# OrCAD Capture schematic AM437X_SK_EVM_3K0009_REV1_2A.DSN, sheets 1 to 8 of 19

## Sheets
1 Pg09: Ethernet #2: size C; title: AM437x Starter Kit EVM; rev: 1.2A; company: Texas Instruments; note: am437x_starterkit_evm_3k0009.dsn; note: Catalog Processors BU; note: Final
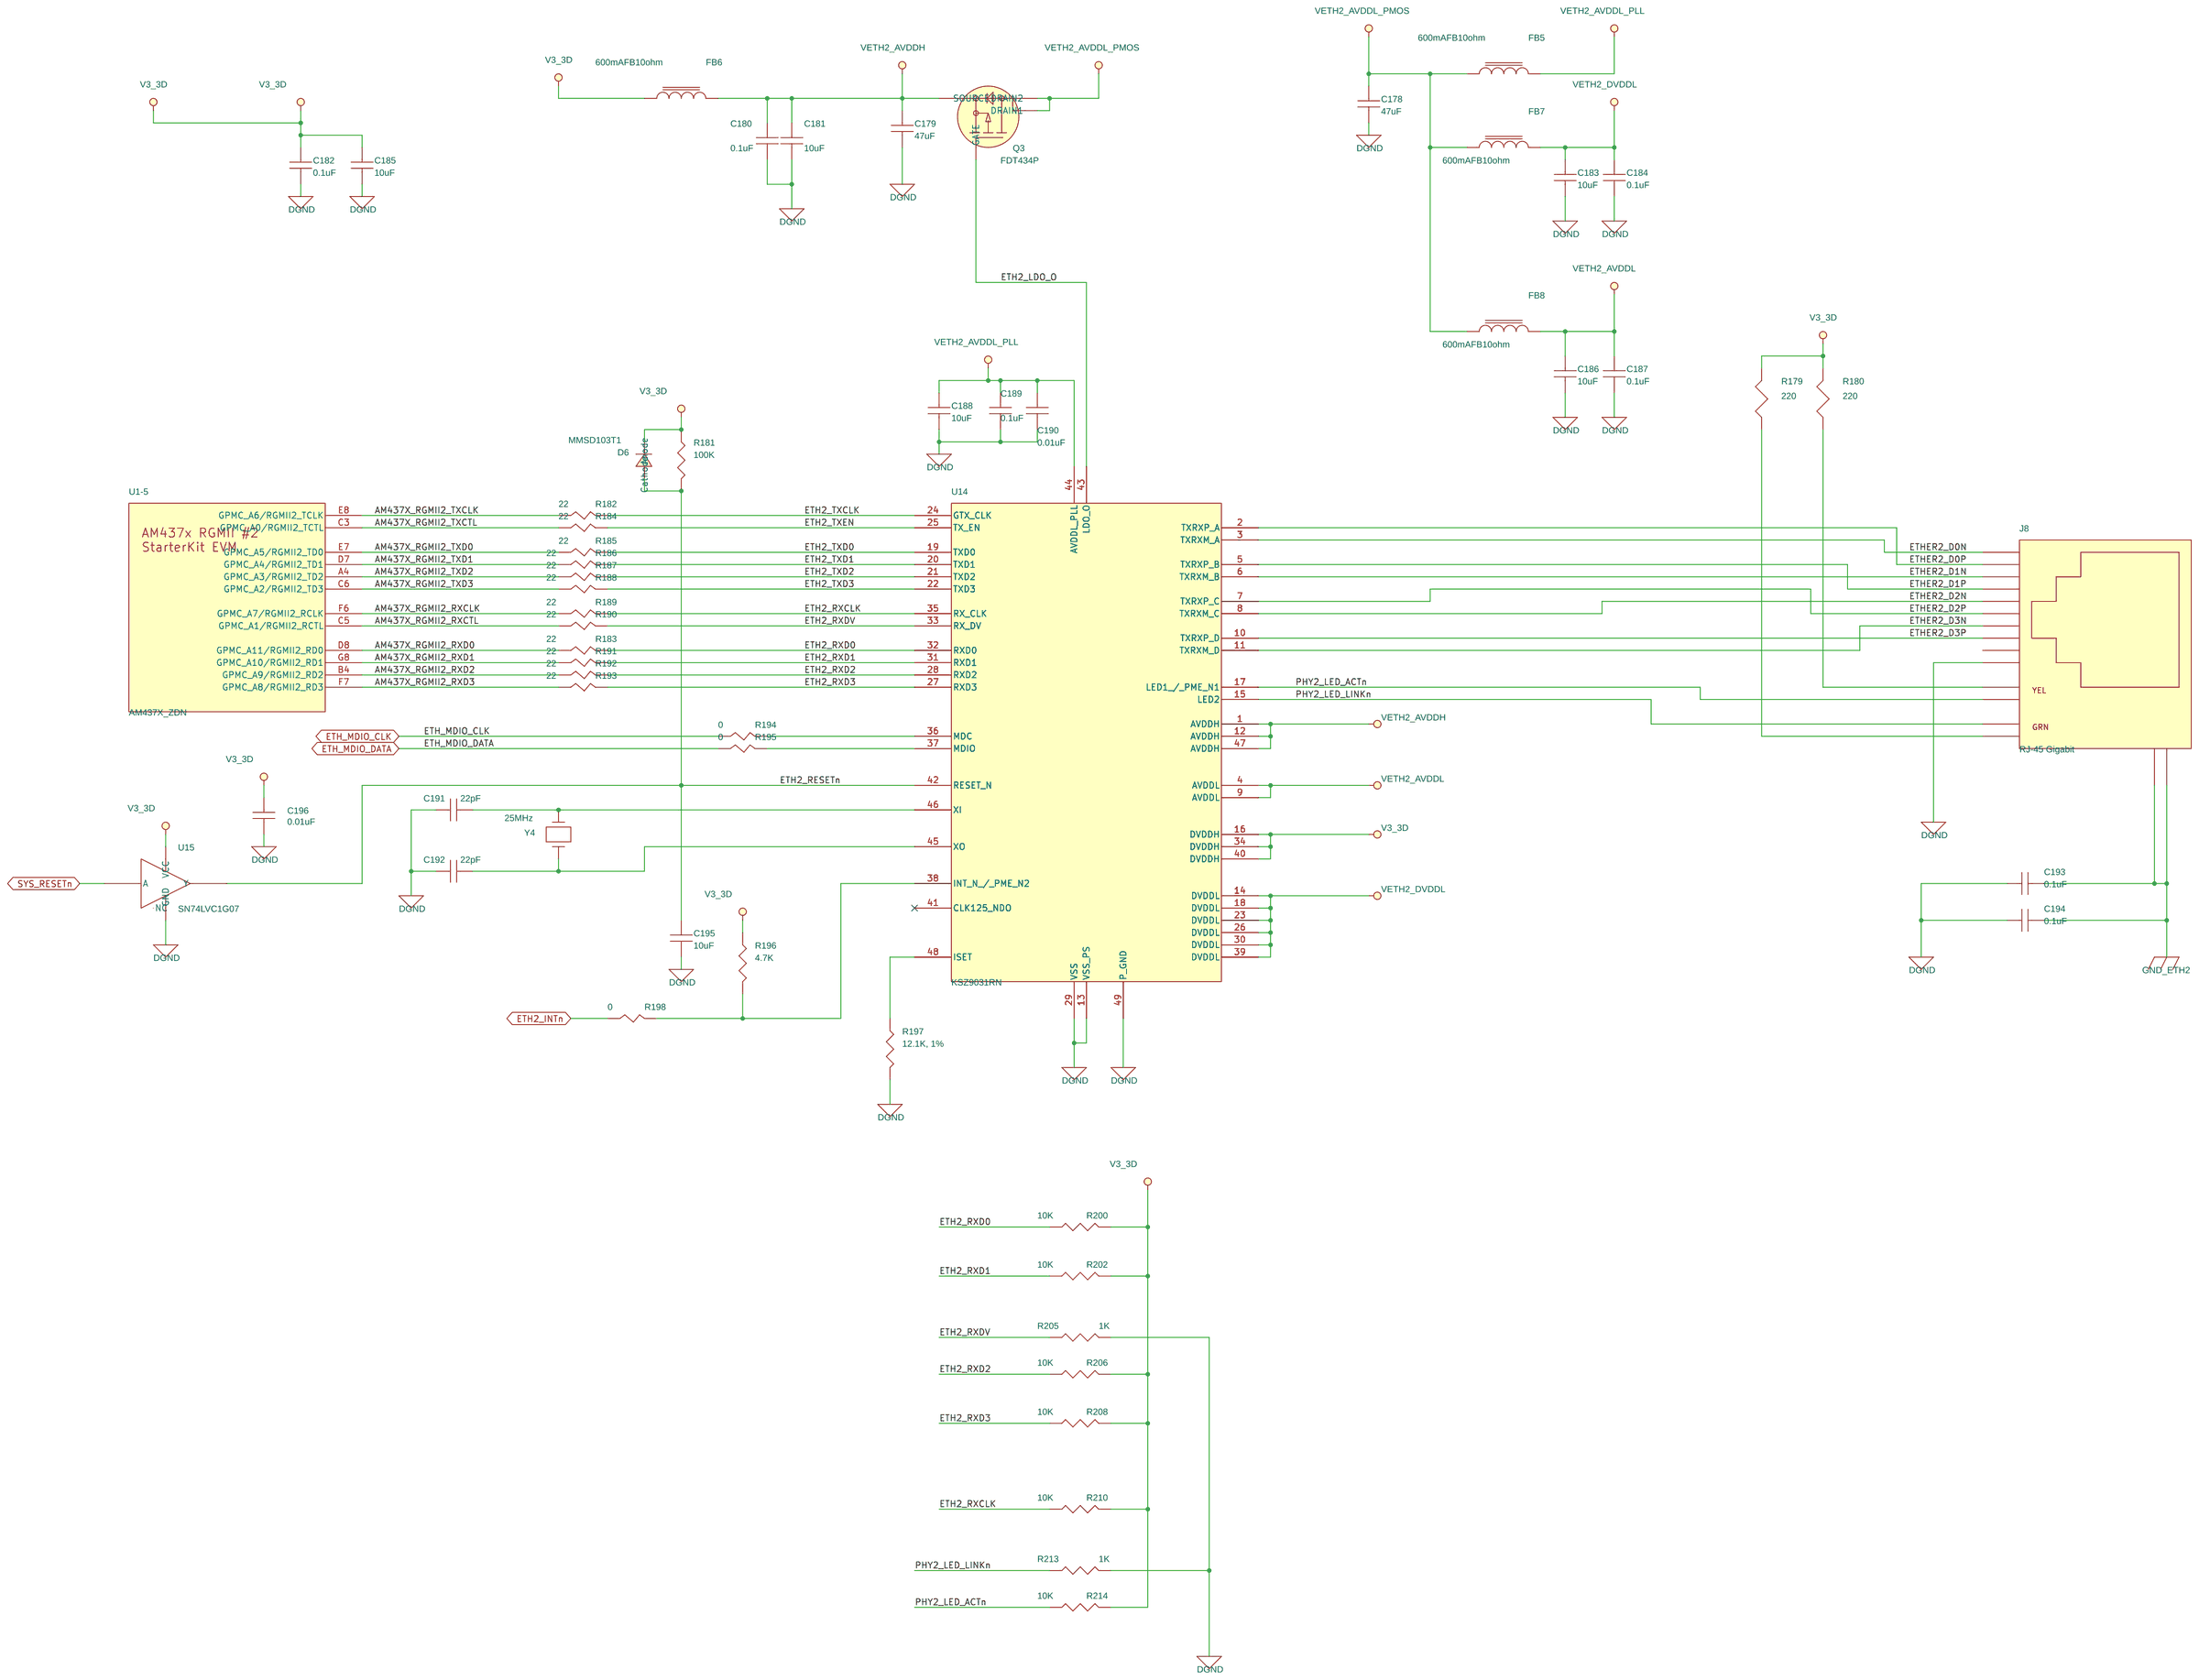
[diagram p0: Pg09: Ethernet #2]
2 Pg01: Title Page
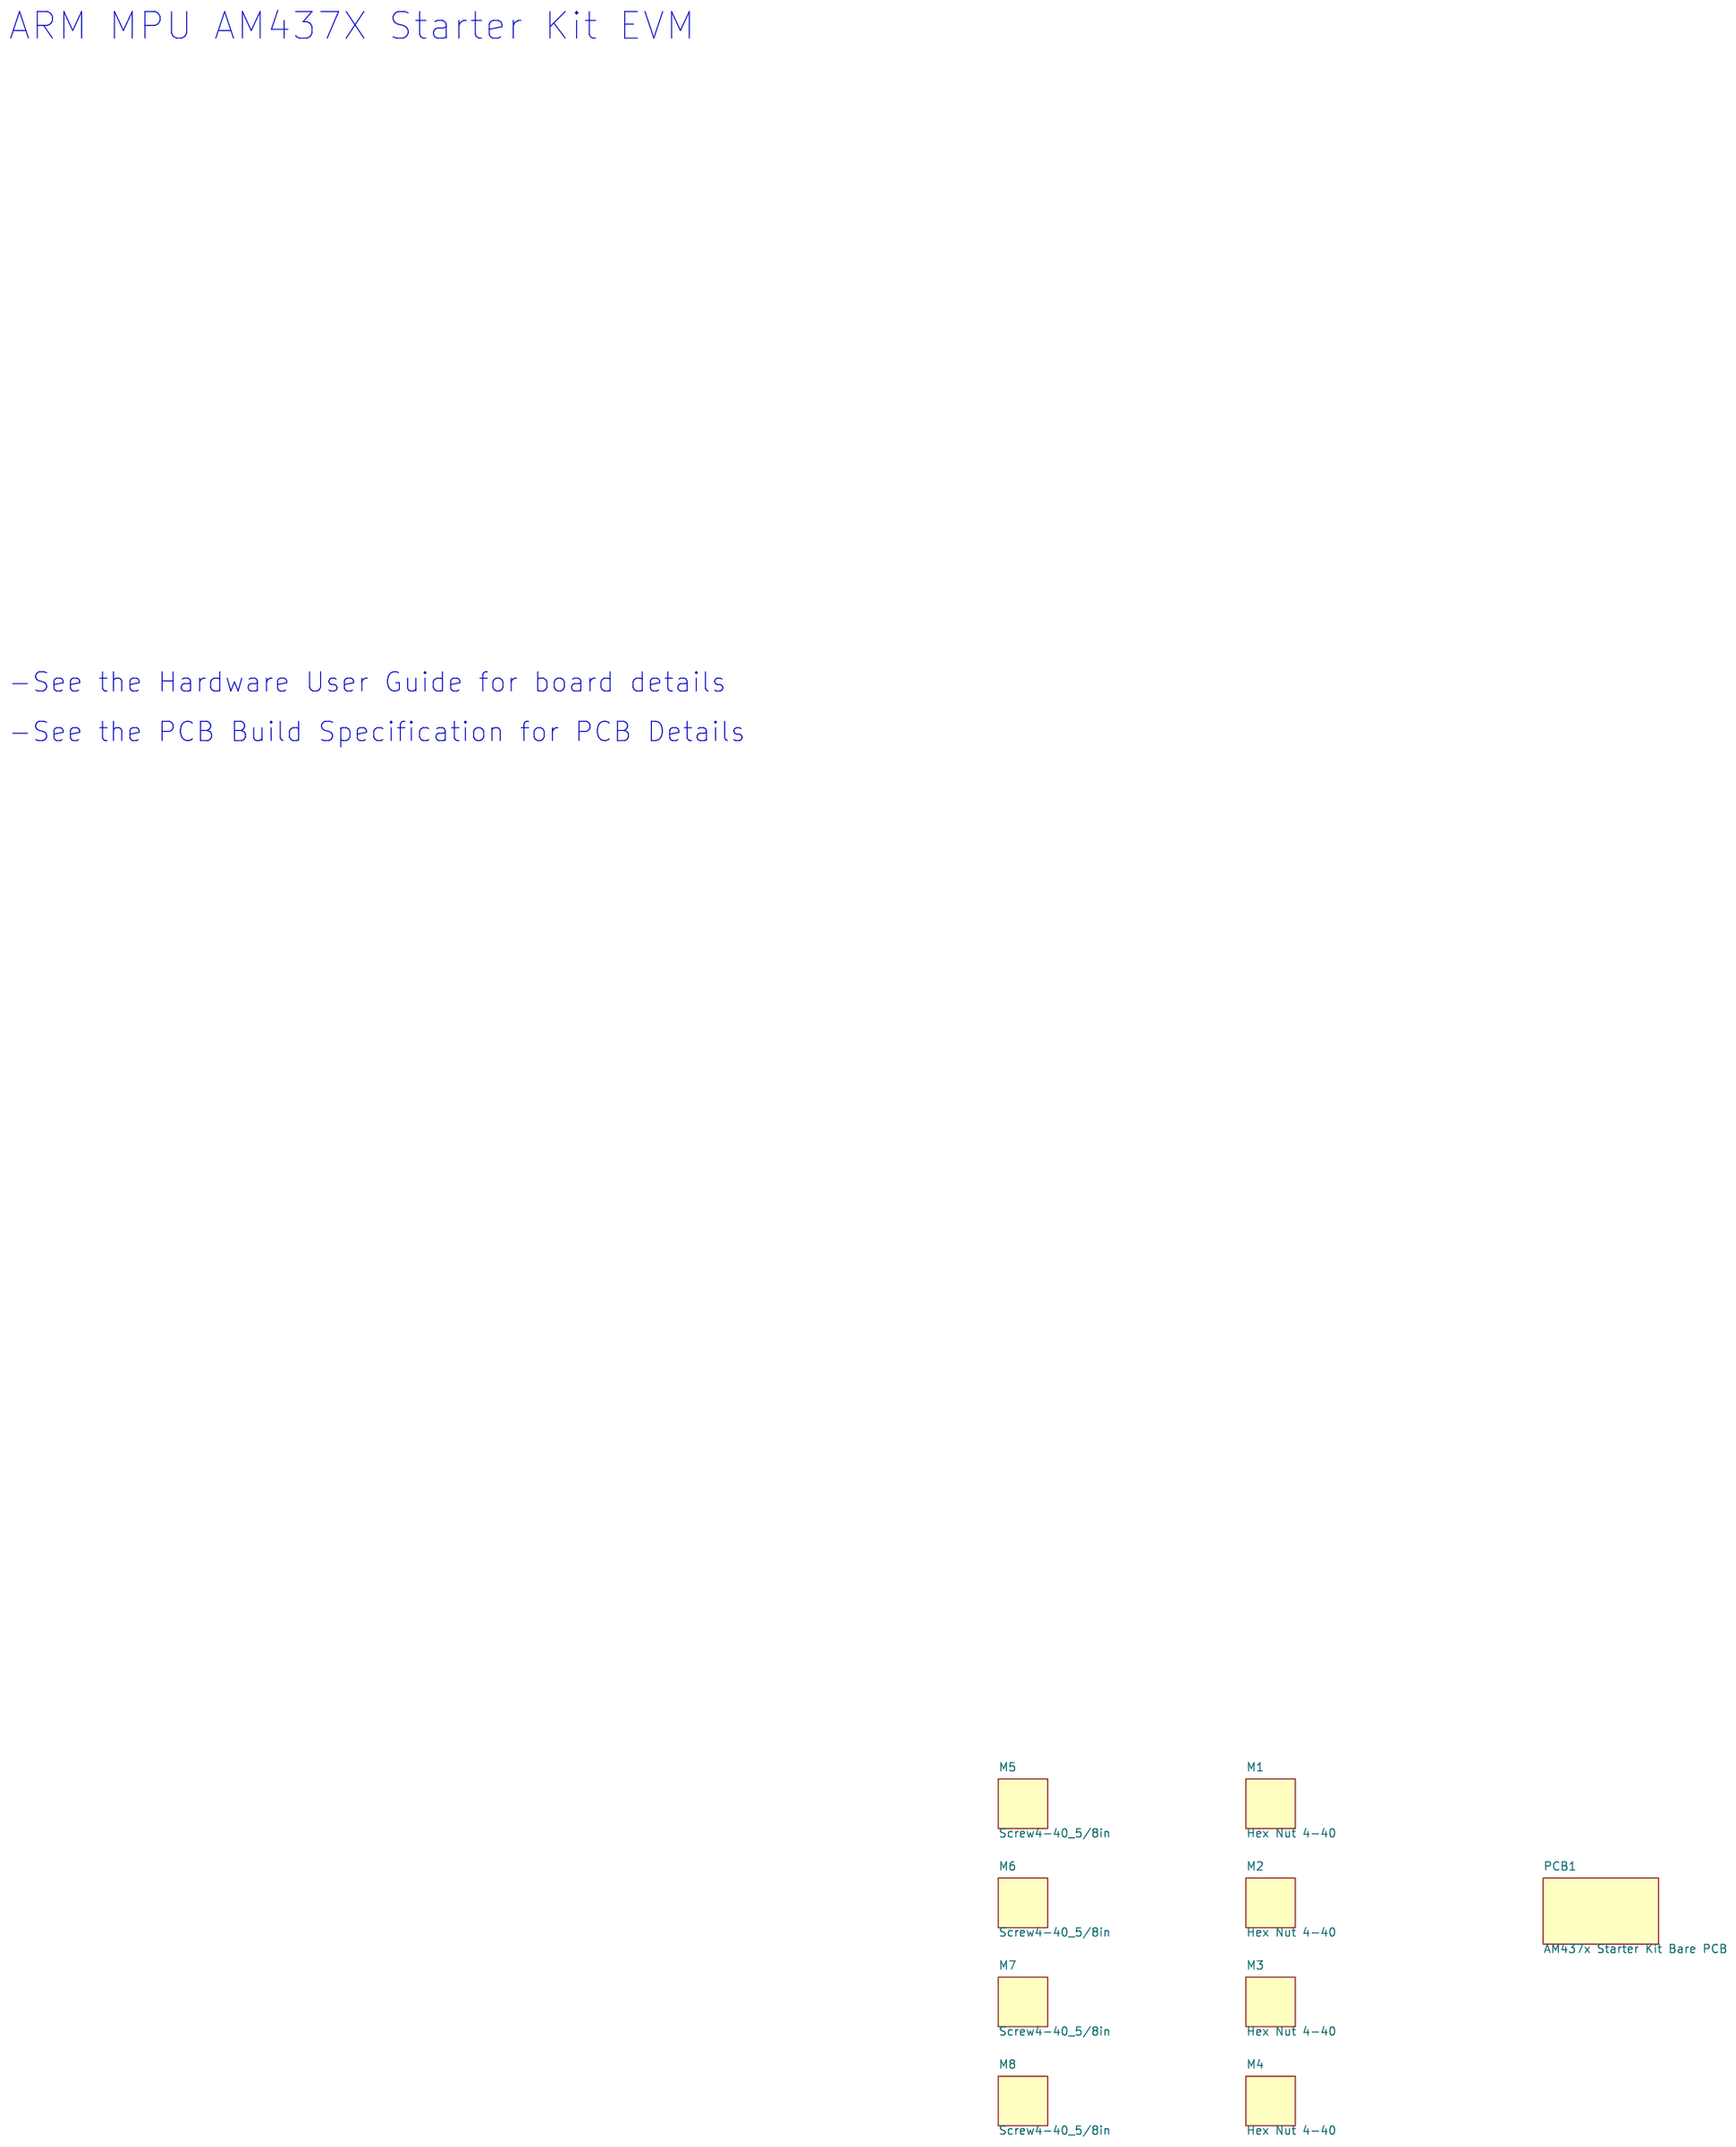
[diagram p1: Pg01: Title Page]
3 Pg12: Camera: size C
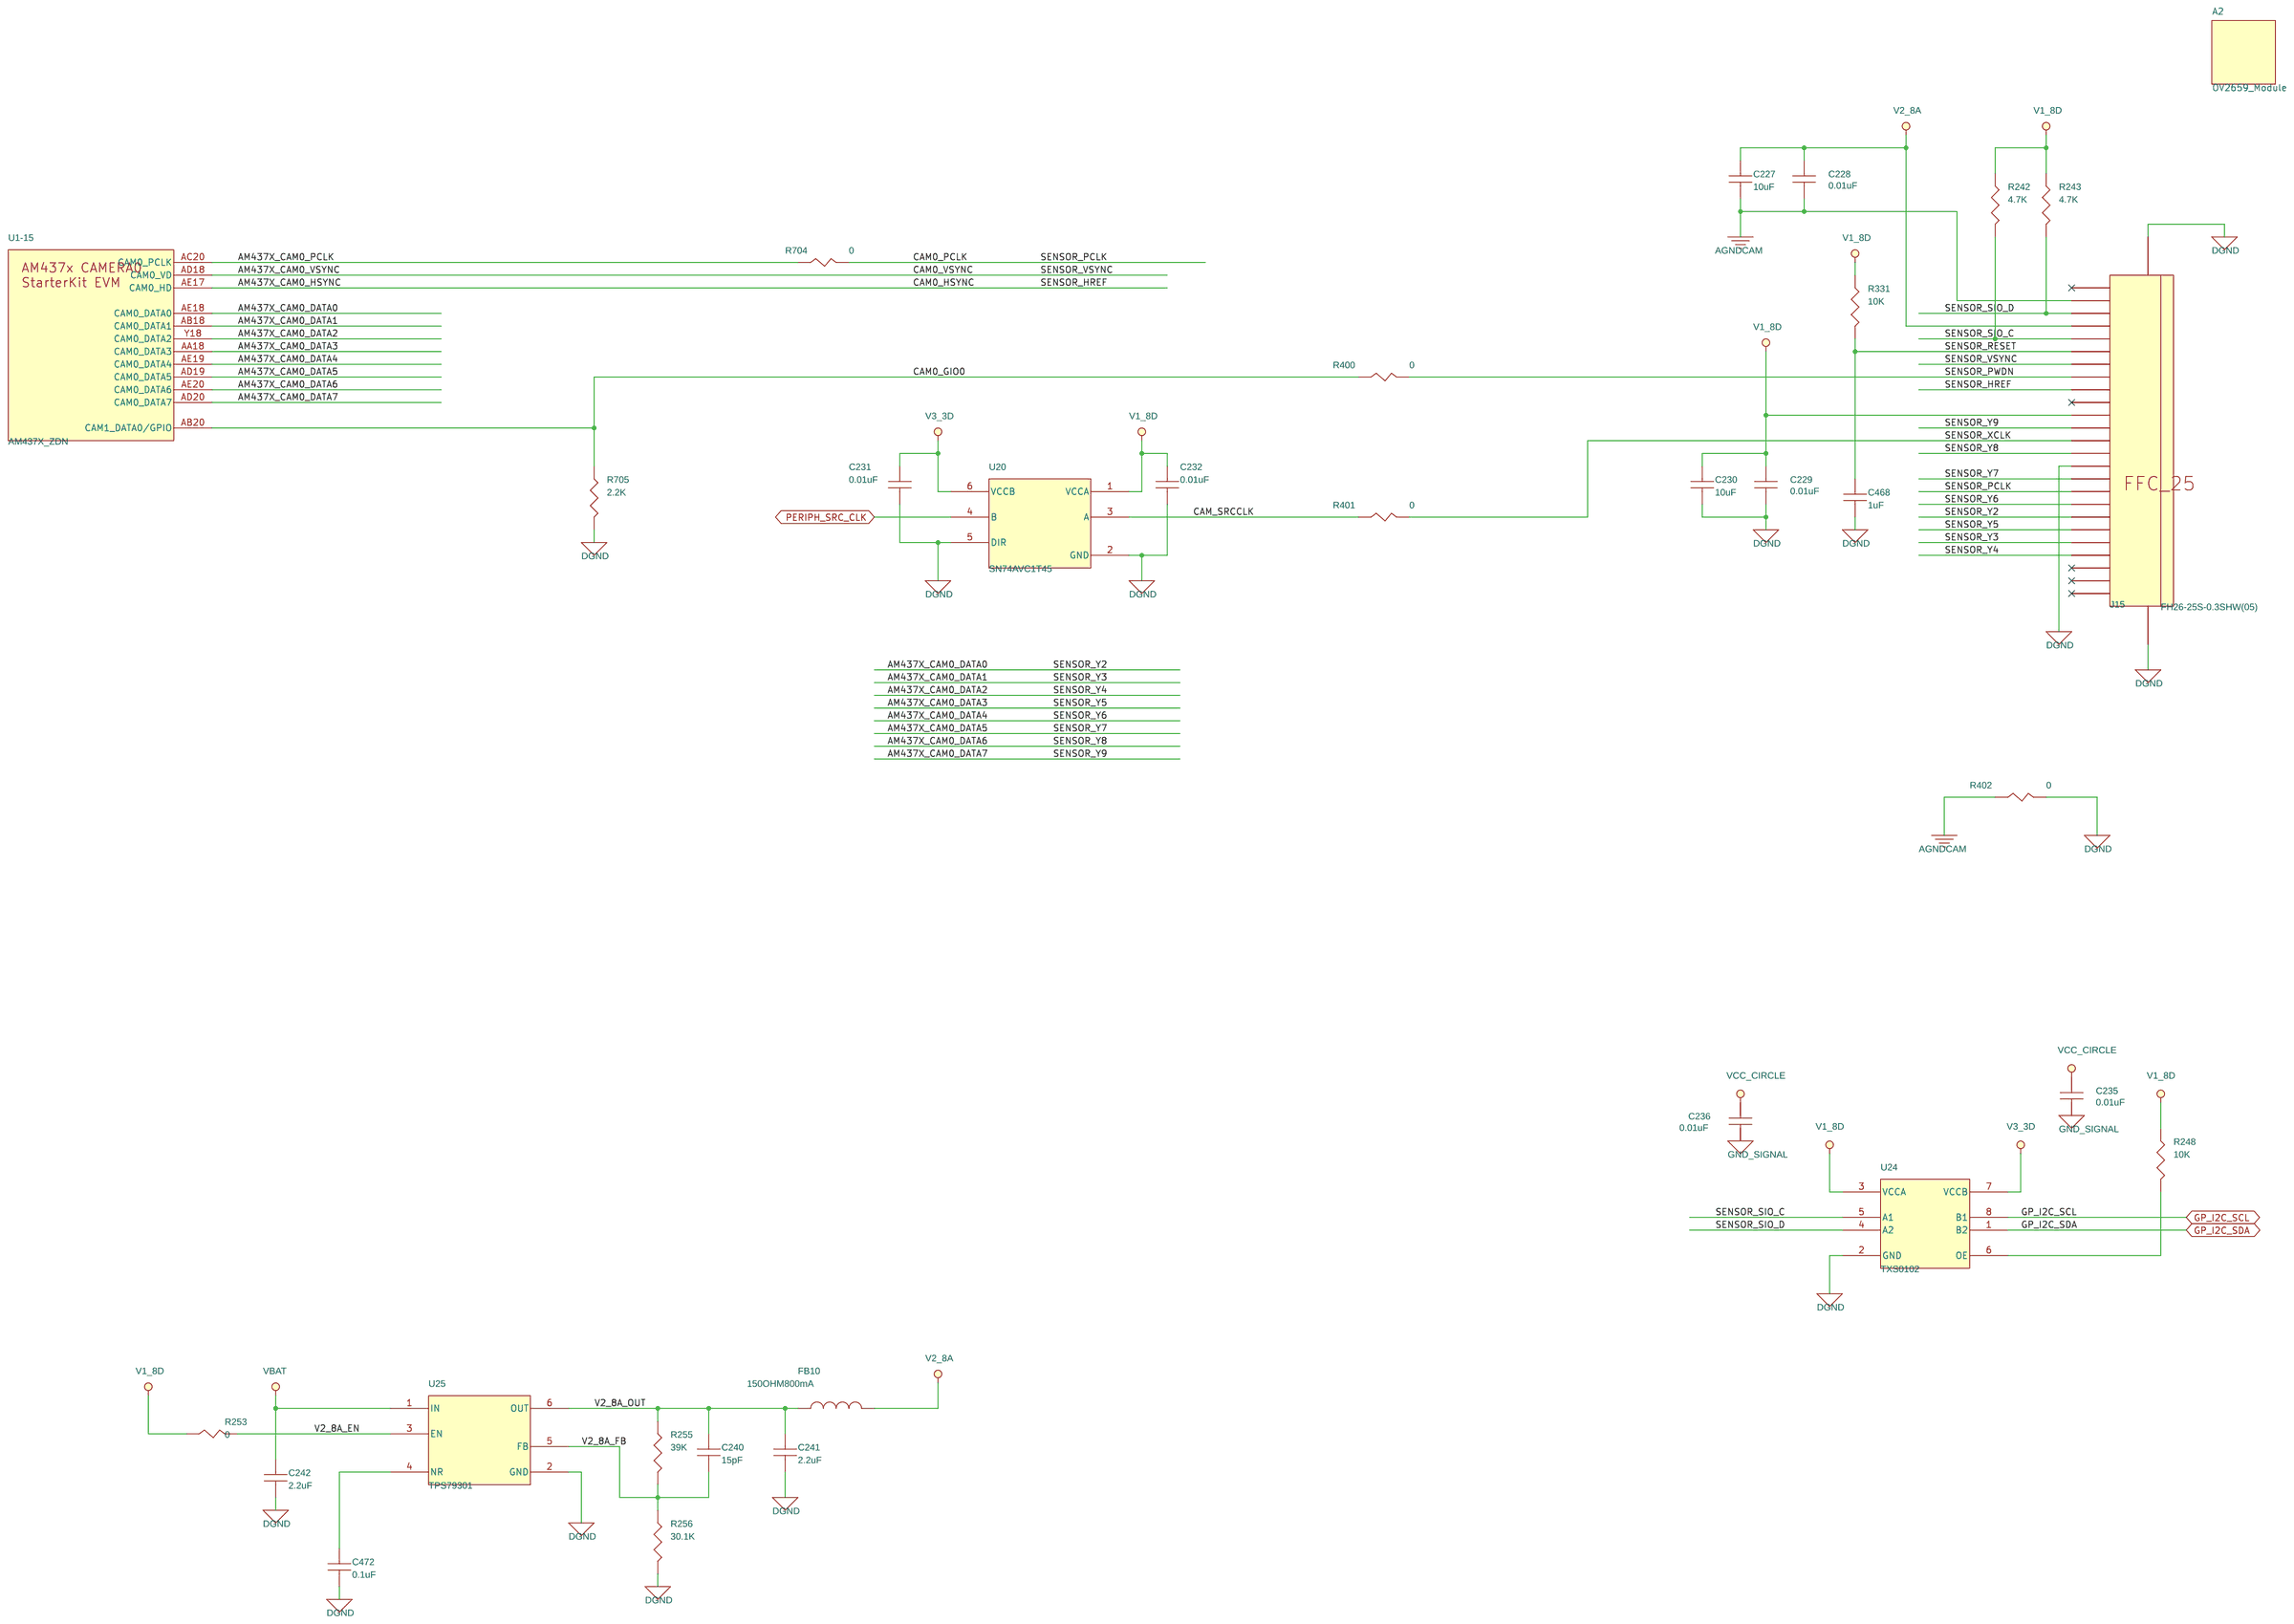
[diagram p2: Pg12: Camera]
4 Pg10: Audio: size C
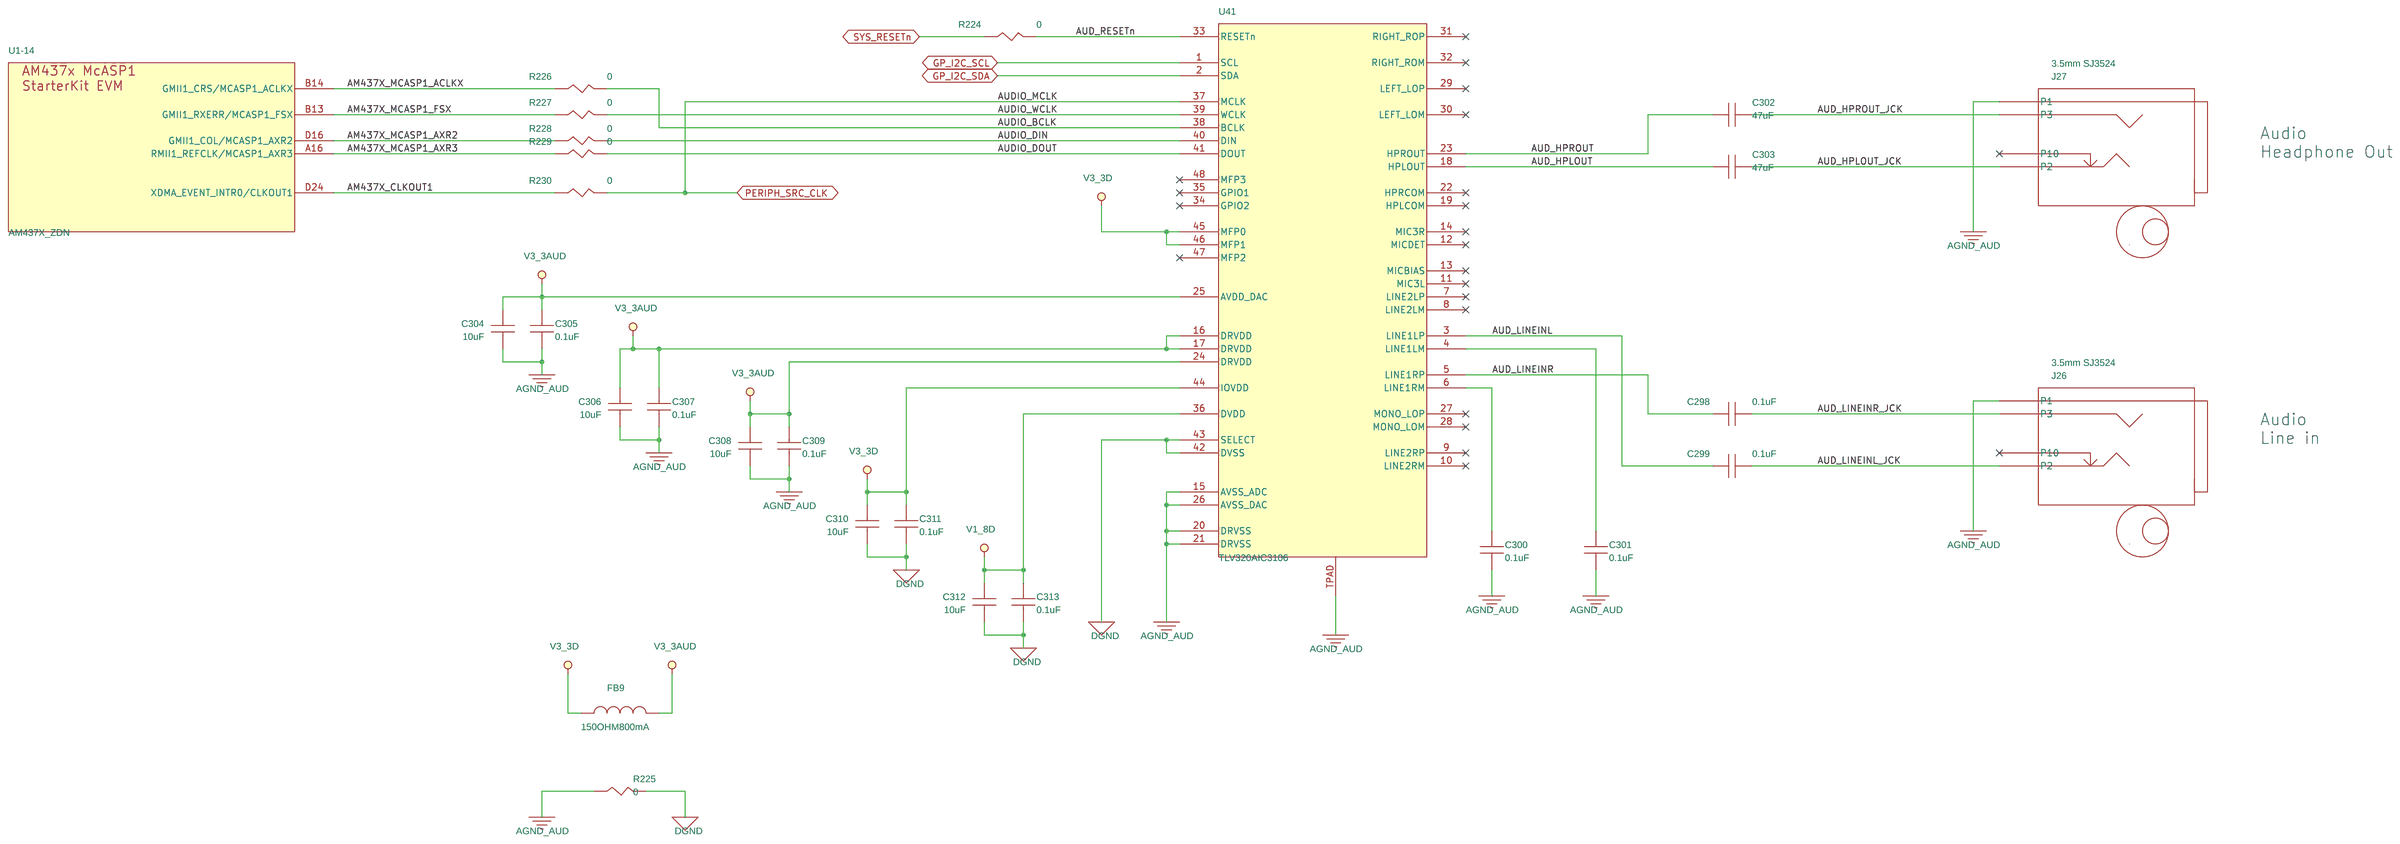
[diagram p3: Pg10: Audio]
5 Pg19: USB JTAG: size C
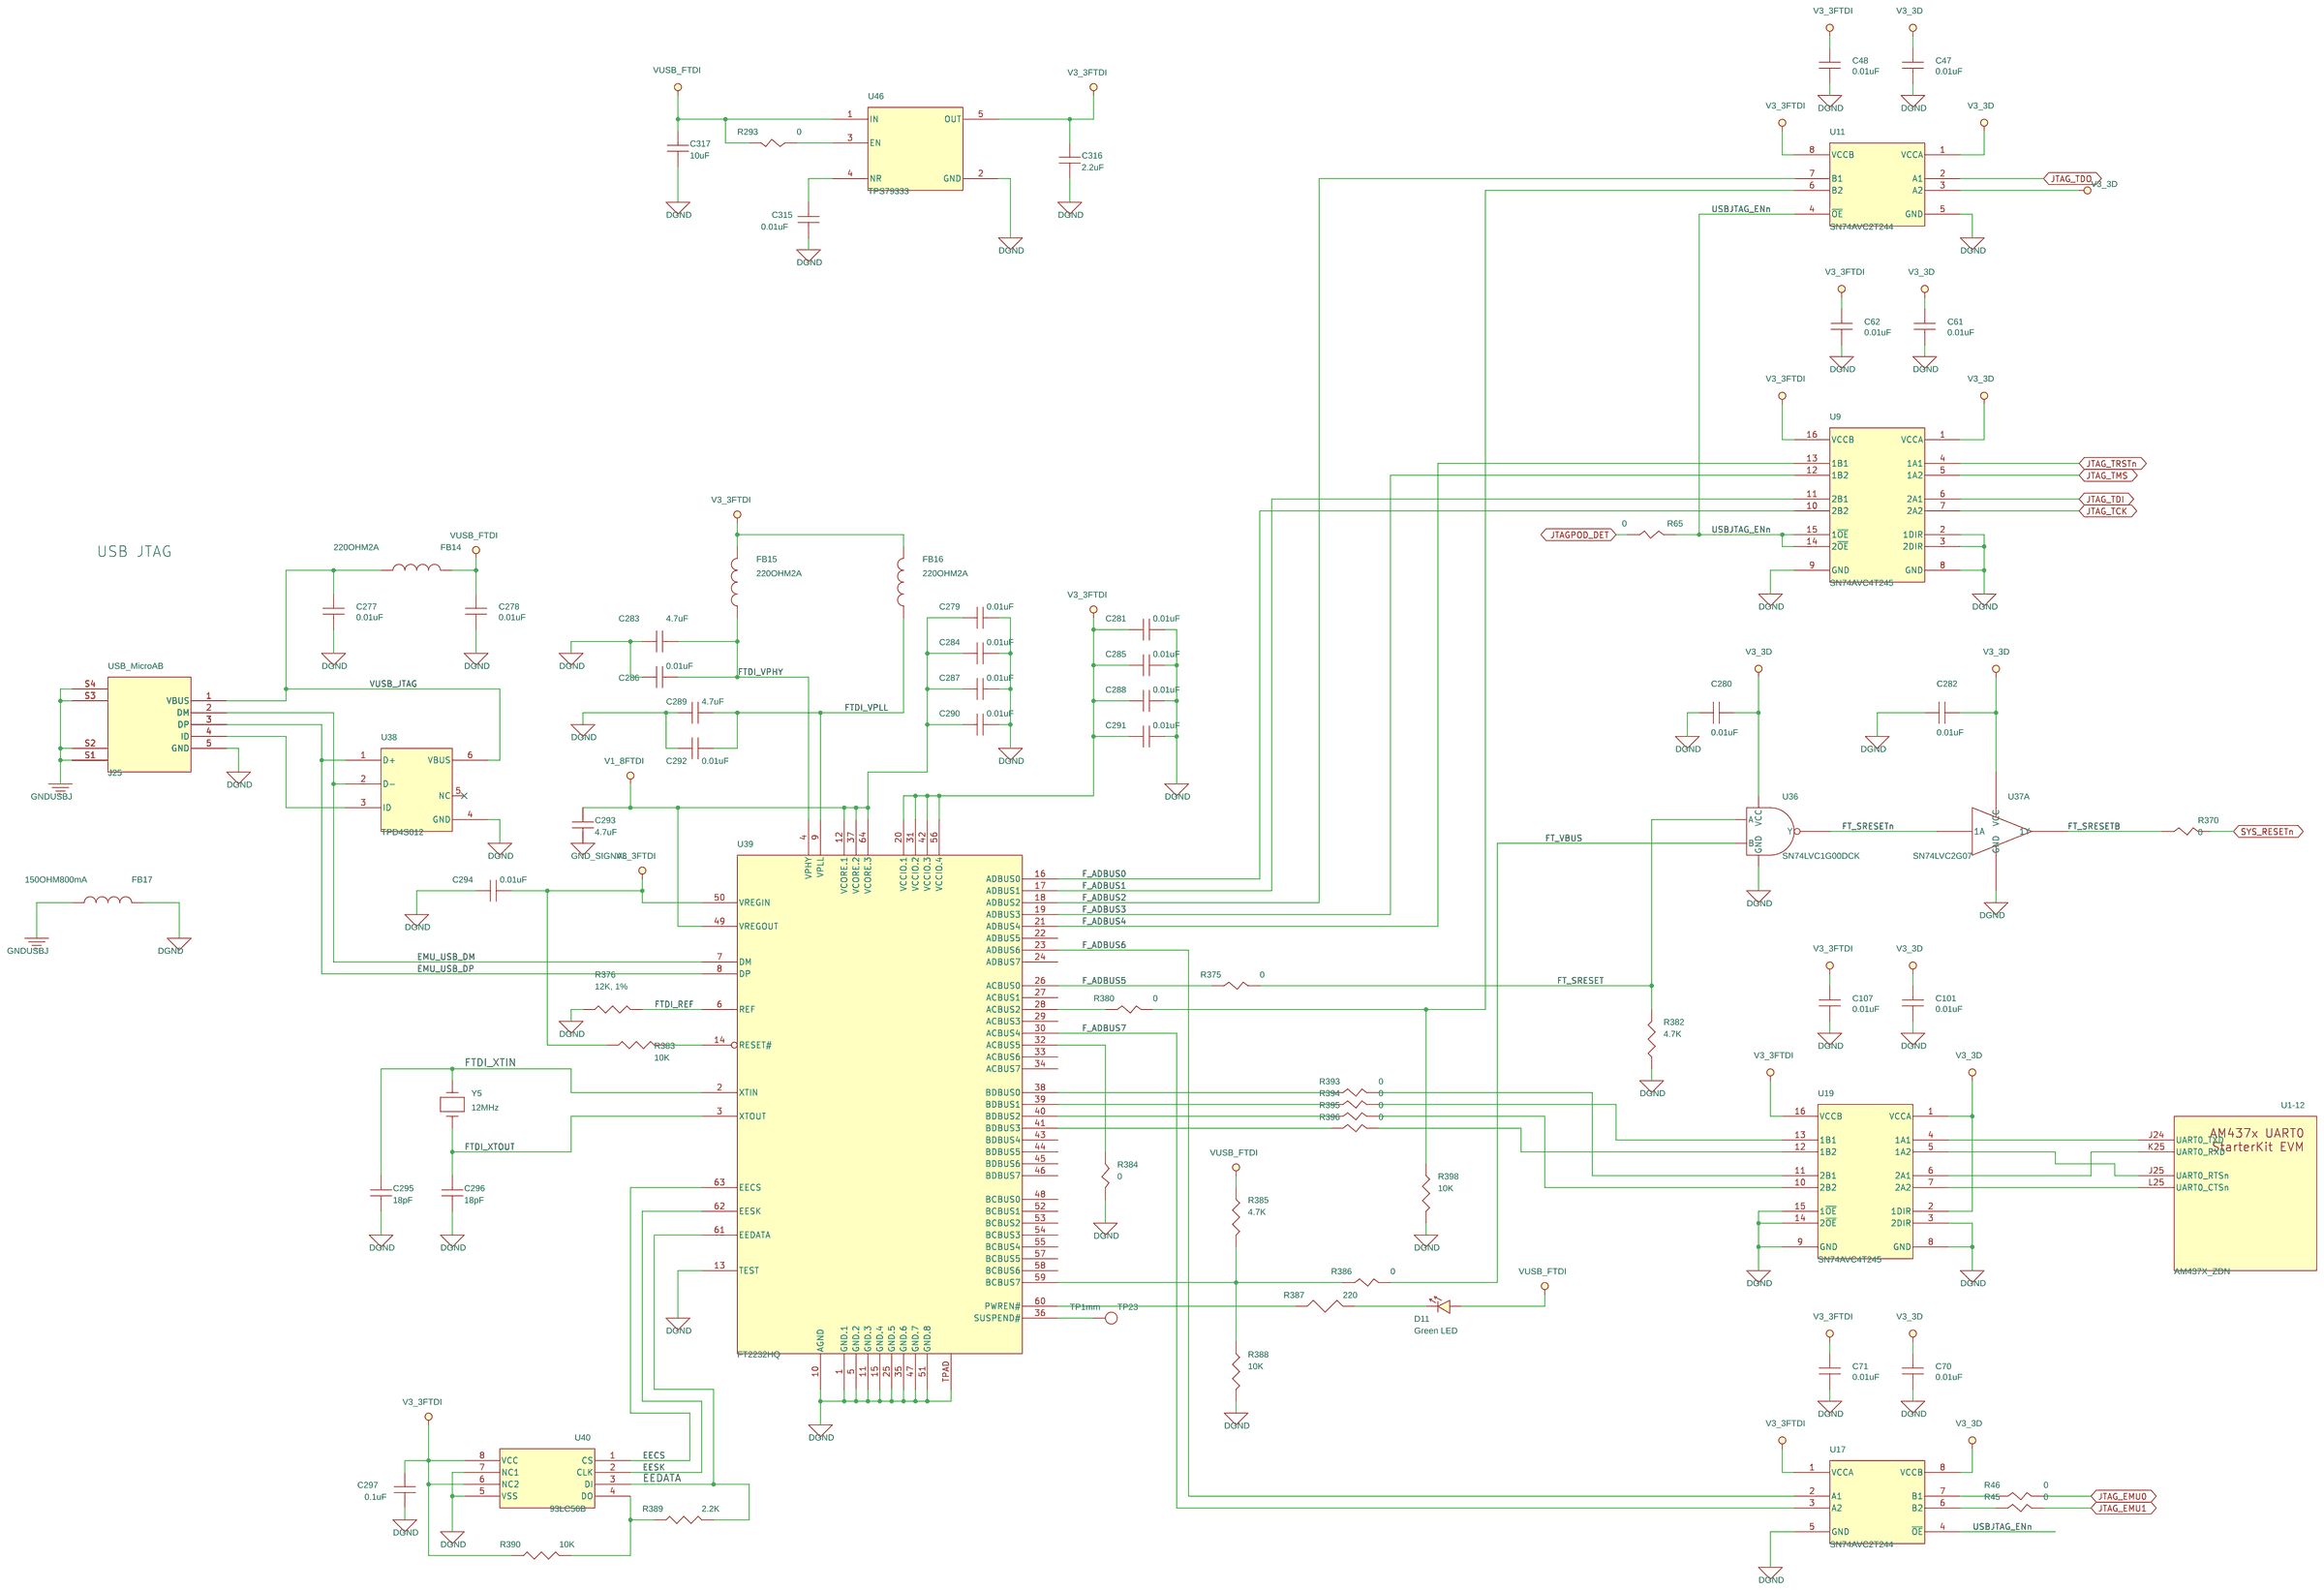
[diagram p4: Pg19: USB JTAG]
6 Pg06: DDR3 Memory: size C
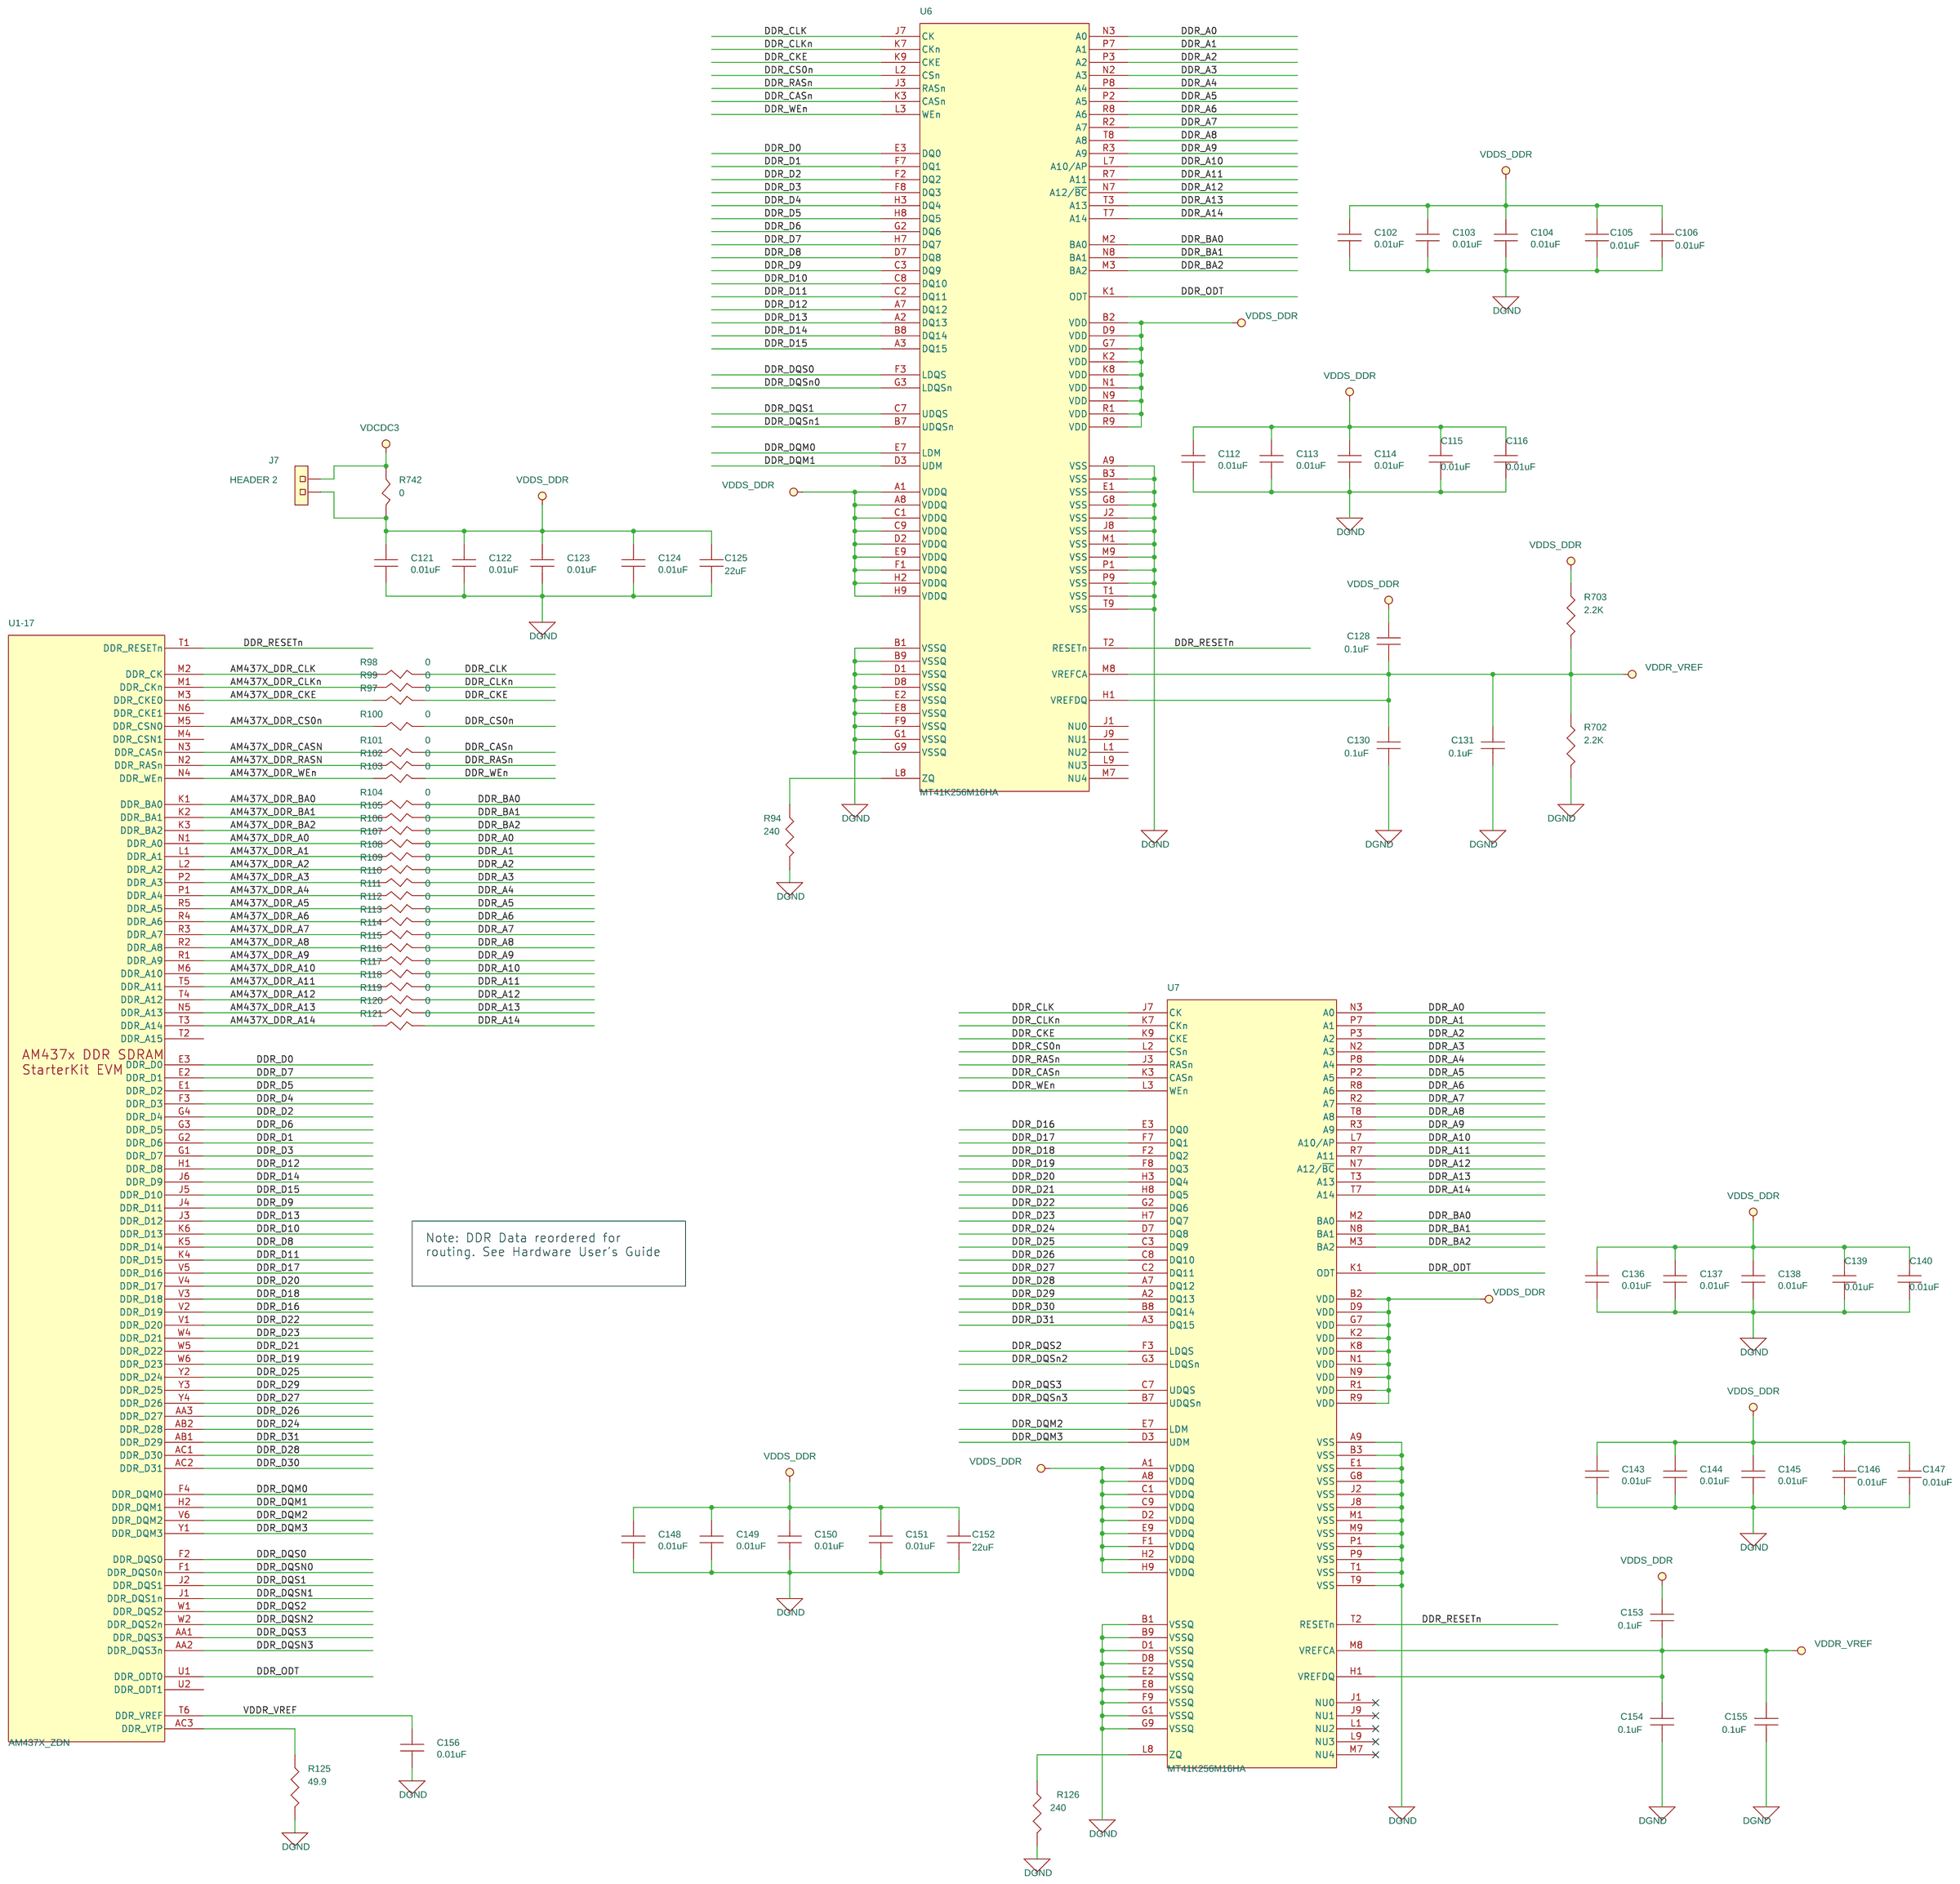
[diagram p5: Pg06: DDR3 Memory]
7 Pg18: JTAG Debug: size C
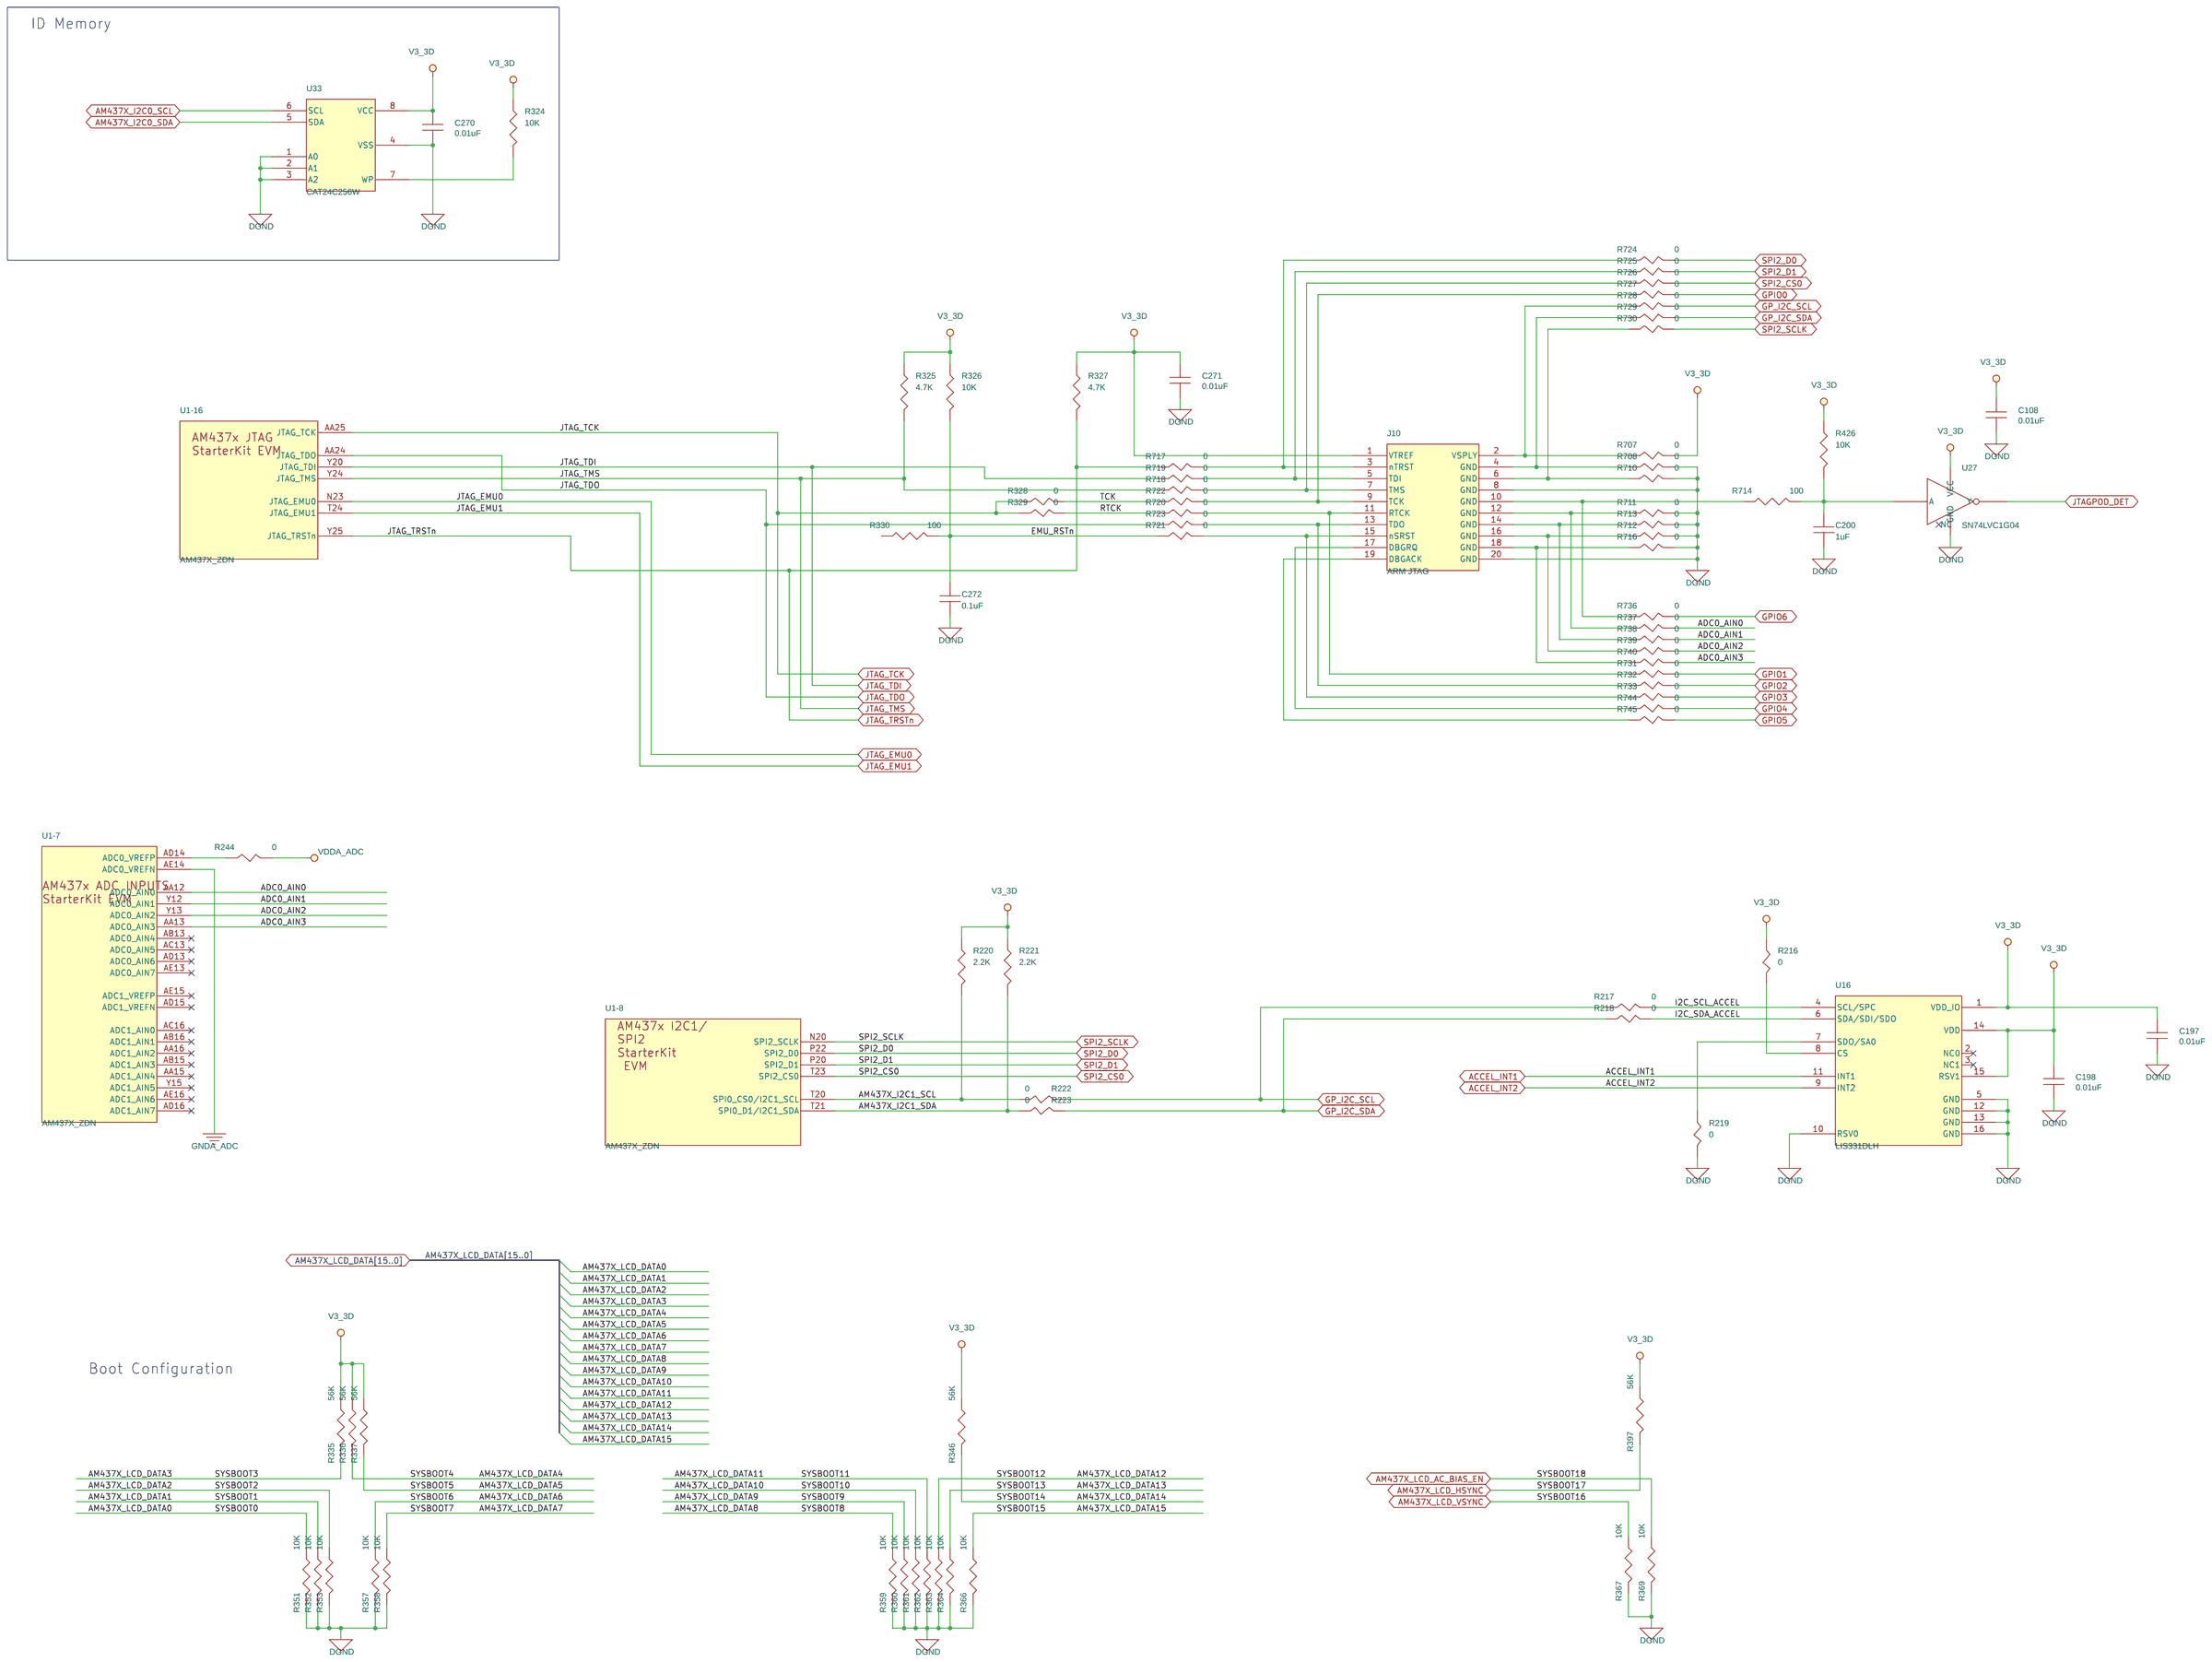
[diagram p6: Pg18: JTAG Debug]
8 Pg08: Ethernet #1: size C
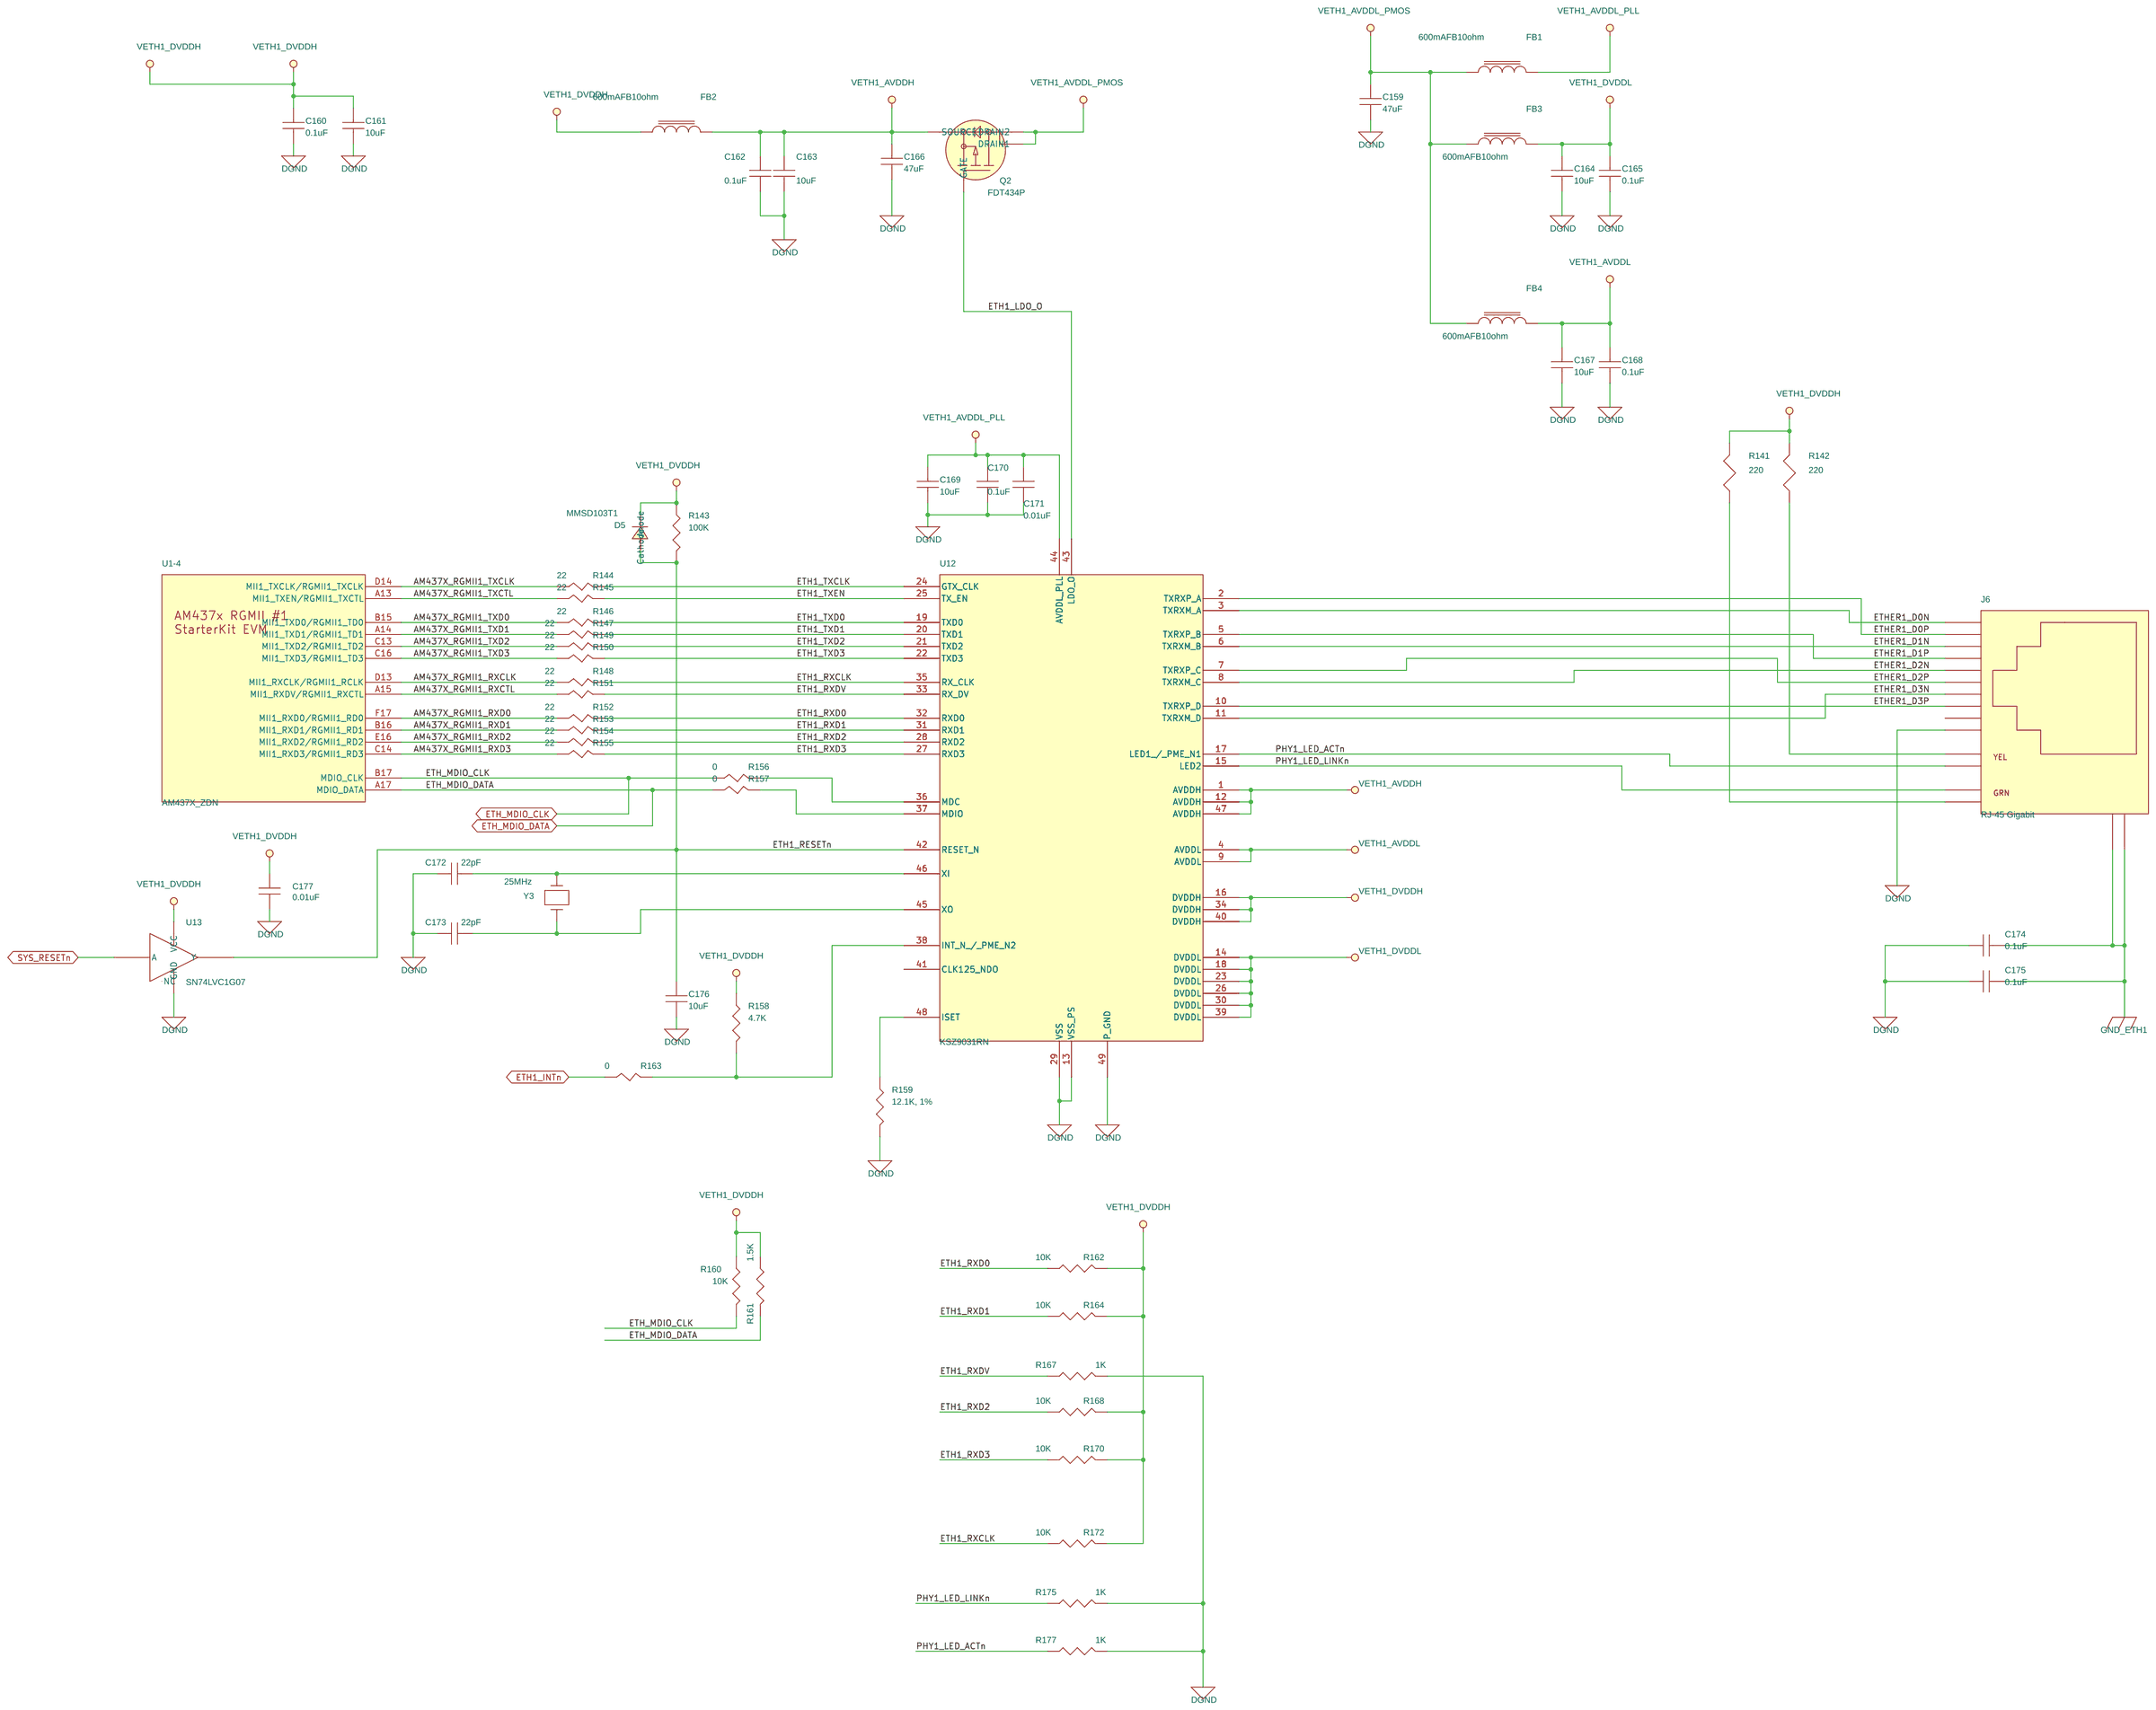
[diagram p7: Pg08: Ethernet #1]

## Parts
sheet Pg01: Title Page
M1  Hex Nut 4-40  [DNP]
M2  Hex Nut 4-40  [DNP]
M3  Hex Nut 4-40  [DNP]
M4  Hex Nut 4-40  [DNP]
M5  Screw4-40_5/8in  [DNP]
M6  Screw4-40_5/8in  [DNP]
M7  Screw4-40_5/8in  [DNP]
M8  Screw4-40_5/8in  [DNP]
PCB1  AM437x Starter Kit Bare PCB  [DNP]
sheet Pg04: Power Supply - PMIC
U1  AM437X_ZDN  [AM437X_ZDN]  (sections -1,-10,-11,-12,-13,-14,-15,-16,-17,-18,-19,-2,-20,-21,-3,-4,-5,-6,-7,-8,-9)
sheet Pg06: DDR3 Memory
C102  0.01uF  [SM-7351-CAP-0402]
C103  0.01uF  [SM-7351-CAP-0402]
C104  0.01uF  [SM-7351-CAP-0402]
C105  0.01uF  [SM-7351-CAP-0402]
C106  0.01uF  [SM-7351-CAP-0402]
C112  0.01uF  [SM-7351-CAP-0402]
C113  0.01uF  [SM-7351-CAP-0402]
C114  0.01uF  [SM-7351-CAP-0402]
C115  0.01uF  [SM-7351-CAP-0402]
C116  0.01uF  [SM-7351-CAP-0402]
C121  0.01uF  [SM-7351-CAP-0402]
C122  0.01uF  [SM-7351-CAP-0402]
C123  0.01uF  [SM-7351-CAP-0402]
C124  0.01uF  [SM-7351-CAP-0402]
C125  22uF  [SM-7351-CAP-0805]
C128  0.1uF  [SM-7351-CAP-0402]
C130  0.1uF  [SM-7351-CAP-0402]
C131  0.1uF  [SM-7351-CAP-0402]
C136  0.01uF  [SM-7351-CAP-0402]
C137  0.01uF  [SM-7351-CAP-0402]
C138  0.01uF  [SM-7351-CAP-0402]
C139  0.01uF  [SM-7351-CAP-0402]
C140  0.01uF  [SM-7351-CAP-0402]
C143  0.01uF  [SM-7351-CAP-0402]
C144  0.01uF  [SM-7351-CAP-0402]
C145  0.01uF  [SM-7351-CAP-0402]
C146  0.01uF  [SM-7351-CAP-0402]
C147  0.01uF  [SM-7351-CAP-0402]
C148  0.01uF  [SM-7351-CAP-0402]
C149  0.01uF  [SM-7351-CAP-0402]
C150  0.01uF  [SM-7351-CAP-0402]
C151  0.01uF  [SM-7351-CAP-0402]
C152  22uF  [SM-7351-CAP-0805]
C153  0.1uF  [SM-7351-CAP-0402]
C154  0.1uF  [SM-7351-CAP-0402]
C155  0.1uF  [SM-7351-CAP-0402]
C156  0.01uF  [SM-7351-CAP-0402]
J7  HEADER 2  [header_2x1]
R94  240  [sm-7351-res-0402]
R97  0  [SM-7351-RES-0402]
R98  0  [SM-7351-RES-0402]
R99  0  [SM-7351-RES-0402]
R100  0  [SM-7351-RES-0402]
R101  0  [SM-7351-RES-0402]
R102  0  [SM-7351-RES-0402]
R103  0  [SM-7351-RES-0402]
R104  0  [SM-7351-RES-0402]
R105  0  [SM-7351-RES-0402]
R106  0  [SM-7351-RES-0402]
R107  0  [SM-7351-RES-0402]
R108  0  [SM-7351-RES-0402]
R109  0  [SM-7351-RES-0402]
R110  0  [SM-7351-RES-0402]
R111  0  [SM-7351-RES-0402]
R112  0  [SM-7351-RES-0402]
R113  0  [SM-7351-RES-0402]
R114  0  [SM-7351-RES-0402]
R115  0  [SM-7351-RES-0402]
R116  0  [SM-7351-RES-0402]
R117  0  [SM-7351-RES-0402]
R118  0  [SM-7351-RES-0402]
R119  0  [SM-7351-RES-0402]
R120  0  [SM-7351-RES-0402]
R121  0  [SM-7351-RES-0402]
R125  49.9  [SM-7351-RES-0402]
R126  240  [sm-7351-res-0402]
R702  2.2K  [sm-7351-res-0402]
R703  2.2K  [sm-7351-res-0402]
R742  0  [SM-7351-RES-0402]
U6  MT41K256M16HA  [bga9x14-96]
U7  MT41K256M16HA  [bga9x14-96]
sheet Pg08: Ethernet #1
C159  47uF  [SM-7351-CAP-1206]
C160  0.1uF  [SM-7351-CAP-0402]
C161  10uF  [SM-7351-CAP-0805]
C162  0.1uF  [SM-7351-CAP-0402]
C163  10uF  [SM-7351-CAP-0805]
C164  10uF  [SM-7351-CAP-0805]
C165  0.1uF  [SM-7351-CAP-0402]
C166  47uF  [SM-7351-CAP-1206]
C167  10uF  [SM-7351-CAP-0805]
C168  0.1uF  [SM-7351-CAP-0402]
C169  10uF  [SM-7351-CAP-0805]
C170  0.1uF  [SM-7351-CAP-0402]
C171  0.01uF  [SM-7351-CAP-0402]
C172  22pF  [SM-7351-CAP-0402]
C173  22pF  [SM-7351-CAP-0402]
C174  0.1uF  [SM-7351-CAP-0402]
C175  0.1uF  [SM-7351-CAP-0402]
C176  10uF  [SM-7351-CAP-0805]
C177  0.01uF  [SM-7351-CAP-0402]
D5  MMSD103T1  [sod-123]
FB1  600mAFB10ohm  [HF70ACB201209]
FB2  600mAFB10ohm  [HF70ACB201209]
FB3  600mAFB10ohm  [HF70ACB201209]
FB4  600mAFB10ohm  [HF70ACB201209]
J6  RJ-45 Gigabit  [cnrj45-1x1wled-598m]
Q2  FDT434P  [SOT223-4]
R141  220  [SM-7351-RES-0402]
R142  220  [SM-7351-RES-0402]
R143  100K  [SM-7351-RES-0402]
R144  22  [SM-7351-RES-0402]
R145  22  [SM-7351-RES-0402]
R146  22  [SM-7351-RES-0402]
R147  22  [SM-7351-RES-0402]
R148  22  [SM-7351-RES-0402]
R149  22  [SM-7351-RES-0402]
R150  22  [SM-7351-RES-0402]
R151  22  [SM-7351-RES-0402]
R152  22  [SM-7351-RES-0402]
R153  22  [SM-7351-RES-0402]
R154  22  [SM-7351-RES-0402]
R155  22  [SM-7351-RES-0402]
R156  0  [SM-7351-RES-0402]
R157  0  [SM-7351-RES-0402]
R158  4.7K  [SM-7351-RES-0402]
R159  12.1K, 1%  [SM-7351-RES-0402]
R160  10K  [SM-7351-RES-0402]
R161  1.5K  [SM-7351-RES-0402]
R162  10K  [SM-7351-RES-0402]
R163  0  [SM-7351-RES-0402]
R164  10K  [SM-7351-RES-0402]
R167  1K  [SM-7351-RES-0402]
R168  10K  [SM-7351-RES-0402]
R170  10K  [SM-7351-RES-0402]
R172  10K  [SM-7351-RES-0402]
R175  1K  [SM-7351-RES-0402]
R177  1K  [SM-7351-RES-0402]
U12  KSZ9031RN  [qfn7x7-48]
U13  SN74LVC1G07  [SC70-5-43M]
Y3  25MHz  [SM_OSC_ABM3]
sheet Pg09: Ethernet #2
C178  47uF  [SM-7351-CAP-1206]
C179  47uF  [SM-7351-CAP-1206]
C180  0.1uF  [SM-7351-CAP-0402]
C181  10uF  [SM-7351-CAP-0805]
C182  0.1uF  [SM-7351-CAP-0402]
C183  10uF  [SM-7351-CAP-0805]
C184  0.1uF  [SM-7351-CAP-0402]
C185  10uF  [SM-7351-CAP-0805]
C186  10uF  [SM-7351-CAP-0805]
C187  0.1uF  [SM-7351-CAP-0402]
C188  10uF  [SM-7351-CAP-0805]
C189  0.1uF  [SM-7351-CAP-0402]
C190  0.01uF  [SM-7351-CAP-0402]
C191  22pF  [SM-7351-CAP-0402]
C192  22pF  [SM-7351-CAP-0402]
C193  0.1uF  [SM-7351-CAP-0402]
C194  0.1uF  [SM-7351-CAP-0402]
C195  10uF  [SM-7351-CAP-0805]
C196  0.01uF  [SM-7351-CAP-0402]
D6  MMSD103T1  [sod-123]
FB5  600mAFB10ohm  [HF70ACB201209]
FB6  600mAFB10ohm  [HF70ACB201209]
FB7  600mAFB10ohm  [HF70ACB201209]
FB8  600mAFB10ohm  [HF70ACB201209]
J8  RJ-45 Gigabit  [cnrj45-1x1wled-598m]
Q3  FDT434P  [SOT223-4]
R179  220  [SM-7351-RES-0402]
R180  220  [SM-7351-RES-0402]
R181  100K  [SM-7351-RES-0402]
R182  22  [SM-7351-RES-0402]
R183  22  [SM-7351-RES-0402]
R184  22  [SM-7351-RES-0402]
R185  22  [SM-7351-RES-0402]
R186  22  [SM-7351-RES-0402]
R187  22  [SM-7351-RES-0402]
R188  22  [SM-7351-RES-0402]
R189  22  [SM-7351-RES-0402]
R190  22  [SM-7351-RES-0402]
R191  22  [SM-7351-RES-0402]
R192  22  [SM-7351-RES-0402]
R193  22  [SM-7351-RES-0402]
R194  0  [SM-7351-RES-0402]
R195  0  [SM-7351-RES-0402]
R196  4.7K  [SM-7351-RES-0402]
R197  12.1K, 1%  [SM-7351-RES-0402]
R198  0  [SM-7351-RES-0402]
R200  10K  [SM-7351-RES-0402]
R202  10K  [SM-7351-RES-0402]
R205  1K  [SM-7351-RES-0402]
R206  10K  [SM-7351-RES-0402]
R208  10K  [SM-7351-RES-0402]
R210  10K  [SM-7351-RES-0402]
R213  1K  [SM-7351-RES-0402]
R214  10K  [SM-7351-RES-0402]
U14  KSZ9031RN  [qfn7x7-48]
U15  SN74LVC1G07  [SC70-5-43M]
Y4  25MHz  [SM_OSC_ABM3]
sheet Pg10: Audio
C298  0.1uF  [SM-7351-CAP-0402]
C299  0.1uF  [SM-7351-CAP-0402]
C300  0.1uF  [SM-7351-CAP-0402]
C301  0.1uF  [SM-7351-CAP-0402]
C302  47uF  [SM-7351-CAP-1206]
C303  47uF  [SM-7351-CAP-1206]
C304  10uF  [SM-7351-CAP-0805]
C305  0.1uF  [SM-7351-CAP-0402]
C306  10uF  [SM-7351-CAP-0805]
C307  0.1uF  [SM-7351-CAP-0402]
C308  10uF  [SM-7351-CAP-0805]
C309  0.1uF  [SM-7351-CAP-0402]
C310  10uF  [SM-7351-CAP-0805]
C311  0.1uF  [SM-7351-CAP-0402]
C312  10uF  [SM-7351-CAP-0805]
C313  0.1uF  [SM-7351-CAP-0402]
FB9  150OHM800mA  [sm-7351-ind-0805]
J26  3.5mm SJ3524  [sj3524smt4pin]
J27  3.5mm SJ3524  [sj3524smt4pin]
R224  0  [SM-7351-RES-0402]
R225  0  [SM-7351-RES-0603]
R226  0  [SM-7351-RES-0402]
R227  0  [SM-7351-RES-0402]
R228  0  [SM-7351-RES-0402]
R229  0  [SM-7351-RES-0402]
R230  0  [SM-7351-RES-0402]
U41  TLV320AIC3106  [vqfn48_rgz]
sheet Pg12: Camera
A2  OV2659_Module  [DNP]
C227  10uF  [SM-7351-CAP-0805]
C228  0.01uF  [SM-7351-CAP-0402]
C229  0.01uF  [SM-7351-CAP-0402]
C230  10uF  [SM-7351-CAP-0805]
C231  0.01uF  [SM-7351-CAP-0402]
C232  0.01uF  [SM-7351-CAP-0402]
C235  0.01uF  [SM-7351-CAP-0402]
C236  0.01uF  [SM-7351-CAP-0402]
C240  15pF  [SM-7351-CAP-0402]
C241  2.2uF  [SM-7351-CAP-0603]
C242  2.2uF  [SM-7351-CAP-0603]
C468  1uF  [SM-7351-CAP-0402]
C472  0.1uF  [SM-7351-CAP-0402]
FB10  150OHM800mA  [sm-7351-ind-0805]
J15  FH26-25S-0.3SHW(05)  [CNFH26-25S]
R242  4.7K  [SM-7351-RES-0402]
R243  4.7K  [SM-7351-RES-0402]
R248  10K  [SM-7351-RES-0402]
R253  0  [SM-7351-RES-0402]
R255  39K  [SM-7351-RES-0402]
R256  30.1K  [SM-7351-RES-0402]
R331  10K  [SM-7351-RES-0402]
R400  0  [SM-7351-RES-0402]
R401  0  [SM-7351-RES-0402]
R402  0  [SM-7351-RES-0402]
R704  0  [SM-7351-RES-0402]
R705  2.2K  [sm-7351-res-0402]
U20  SN74AVC1T45  [smdsc70-6]
U24  TXS0102  [dct8]
U25  TPS79301  [U_6_DBV]
sheet Pg18: JTAG Debug
C108  0.01uF  [SM-7351-CAP-0402]
C197  0.01uF  [SM-7351-CAP-0402]
C198  0.01uF  [SM-7351-CAP-0402]
C200  1uF  [SM-7351-CAP-0402]
C270  0.01uF  [SM-7351-CAP-0402]
C271  0.01uF  [SM-7351-CAP-0402]
C272  0.1uF  [SM-7351-CAP-0402]
J10  ARM JTAG  [hdr2x10-330m]
R216  0  [SM-7351-RES-0402]
R217  0  [SM-7351-RES-0402]
R218  0  [SM-7351-RES-0402]
R219  0  [SM-7351-RES-0402]
R220  2.2K  [sm-7351-res-0402]
R221  2.2K  [sm-7351-res-0402]
R222  0  [SM-7351-RES-0402]
R223  0  [SM-7351-RES-0402]
R244  0  [SM-7351-RES-0402]
R324  10K  [SM-7351-RES-0402]
R325  4.7K  [SM-7351-RES-0402]
R326  10K  [SM-7351-RES-0402]
R327  4.7K  [SM-7351-RES-0402]
R328  0  [SM-7351-RES-0402]
R329  0  [SM-7351-RES-0402]
R330  100  [SM-7351-RES-0402]
R335  56K  [SM-7351-RES-0402]
R336  56K  [SM-7351-RES-0402]
R337  56K  [SM-7351-RES-0402]
R346  56K  [SM-7351-RES-0402]
R351  10K  [SM-7351-RES-0402]
R352  10K  [SM-7351-RES-0402]
R353  10K  [SM-7351-RES-0402]
R357  10K  [SM-7351-RES-0402]
R358  10K  [SM-7351-RES-0402]
R359  10K  [SM-7351-RES-0402]
R360  10K  [SM-7351-RES-0402]
R361  10K  [SM-7351-RES-0402]
R362  10K  [SM-7351-RES-0402]
R363  10K  [SM-7351-RES-0402]
R364  10K  [SM-7351-RES-0402]
R366  10K  [SM-7351-RES-0402]
R367  10K  [SM-7351-RES-0402]
R369  10K  [SM-7351-RES-0402]
R397  56K  [SM-7351-RES-0402]
R426  10K  [SM-7351-RES-0402]
R707  0  [SM-7351-RES-0402]
R708  0  [SM-7351-RES-0402]
R710  0  [SM-7351-RES-0402]
R711  0  [SM-7351-RES-0402]
R712  0  [SM-7351-RES-0402]
R713  0  [SM-7351-RES-0402]
R714  100  [SM-7351-RES-0402]
R716  0  [SM-7351-RES-0402]
R717  0  [SM-7351-RES-0402]
R718  0  [SM-7351-RES-0402]
R719  0  [SM-7351-RES-0402]
R720  0  [SM-7351-RES-0402]
R721  0  [SM-7351-RES-0402]
R722  0  [SM-7351-RES-0402]
R723  0  [SM-7351-RES-0402]
R724  0  [SM-7351-RES-0402]
R725  0  [SM-7351-RES-0402]
R726  0  [SM-7351-RES-0402]
R727  0  [SM-7351-RES-0402]
R728  0  [SM-7351-RES-0402]
R729  0  [SM-7351-RES-0402]
R730  0  [SM-7351-RES-0402]
R731  0  [SM-7351-RES-0402]
R732  0  [SM-7351-RES-0402]
R733  0  [SM-7351-RES-0402]
R736  0  [SM-7351-RES-0402]
R737  0  [SM-7351-RES-0402]
R738  0  [SM-7351-RES-0402]
R739  0  [SM-7351-RES-0402]
R740  0  [SM-7351-RES-0402]
R744  0  [SM-7351-RES-0402]
R745  0  [SM-7351-RES-0402]
U16  LIS331DLH  [LGA16pin_3x3]
U27  SN74LVC1G04  [SC70-5-43M]
U33  CAT24C256W  [SOIC_8]
sheet Pg19: USB JTAG
C47  0.01uF  [SM-7351-CAP-0402]
C48  0.01uF  [SM-7351-CAP-0402]
C61  0.01uF  [SM-7351-CAP-0402]
C62  0.01uF  [SM-7351-CAP-0402]
C70  0.01uF  [SM-7351-CAP-0402]
C71  0.01uF  [SM-7351-CAP-0402]
C101  0.01uF  [SM-7351-CAP-0402]
C107  0.01uF  [SM-7351-CAP-0402]
C277  0.01uF  [SM-7351-CAP-0402]
C278  0.01uF  [SM-7351-CAP-0402]
C279  0.01uF  [SM-7351-CAP-0402]
C280  0.01uF  [SM-7351-CAP-0402]
C281  0.01uF  [SM-7351-CAP-0402]
C282  0.01uF  [SM-7351-CAP-0402]
C283  4.7uF  [SM-7351-CAP-0603]
C284  0.01uF  [SM-7351-CAP-0402]
C285  0.01uF  [SM-7351-CAP-0402]
C286  0.01uF  [SM-7351-CAP-0402]
C287  0.01uF  [SM-7351-CAP-0402]
C288  0.01uF  [SM-7351-CAP-0402]
C289  4.7uF  [SM-7351-CAP-0603]
C290  0.01uF  [SM-7351-CAP-0402]
C291  0.01uF  [SM-7351-CAP-0402]
C292  0.01uF  [SM-7351-CAP-0402]
C293  4.7uF  [SM-7351-CAP-0603]
C294  0.01uF  [SM-7351-CAP-0402]
C295  18pF  [SM-7351-CAP-0402]
C296  18pF  [SM-7351-CAP-0402]
C297  0.1uF  [SM-7351-CAP-0402]
C315  0.01uF  [SM-7351-CAP-0402]
C316  2.2uF  [SM-7351-CAP-0805]
C317  10uF  [SM-7351-CAP-0805]
D11  Green LED  [sm_led_0805]
FB14  220OHM2A  [sm-7351-ind-0603]
FB15  220OHM2A  [sm-7351-ind-0603]
FB16  220OHM2A  [sm-7351-ind-0603]
FB17  150OHM800mA  [sm-7351-ind-0805]
J25  USB_MicroAB  [ZX62-AB-5PA]
R45  0  [SM-7351-RES-0402]
R46  0  [SM-7351-RES-0402]
R65  0  [SM-7351-RES-0402]
R293  0  [SM-7351-RES-0402]
R370  0  [SM-7351-RES-0402]
R375  0  [SM-7351-RES-0402]
R376  12K, 1%  [SM-7351-RES-0402]
R380  0  [SM-7351-RES-0402]
R382  4.7K  [SM-7351-RES-0402]
R383  10K  [SM-7351-RES-0402]
R384  0  [SM-7351-RES-0402]
R385  4.7K  [SM-7351-RES-0402]
R386  0  [SM-7351-RES-0402]
R387  220  [SM-7351-RES-0402]
R388  10K  [SM-7351-RES-0402]
R389  2.2K  [sm-7351-res-0402]
R390  10K  [SM-7351-RES-0402]
R393  0  [SM-7351-RES-0402]
R394  0  [SM-7351-RES-0402]
R395  0  [SM-7351-RES-0402]
R396  0  [SM-7351-RES-0402]
R398  10K  [SM-7351-RES-0402]
TP23  TP1mm  [tp_smd1mmcircle]
U9  SN74AVC4T245  [U_16_PW]
U11  SN74AVC2T244  [son2x1-8-16m]
U17  SN74AVC2T244  [son2x1-8-16m]
U19  SN74AVC4T245  [U_16_PW]
U36  SN74LVC1G00DCK  [U_5_DCK]
U37  SN74LVC2G07  [U_6_DCK]  (section A)
U38  TPD4S012  [U_6_DRY]
U39  FT2232HQ  [QFN9X9-64-39M]
U40  93LC56B  [soic8]
U46  TPS79333  [U_5_DBV]
Y5  12MHz  [SM_OSC_ABM3]

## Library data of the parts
M1-M4 = 2M_HexNut_4-40_steel
M5-M8 = 2M_Screw_4-40_5_8
PCB1 = 3K_AM437xStarterKitBarePCB: Version: 1.1A
U1 = AM437x_ZDN_StarterKit: Color: Default; Cost100: 5.01; Cost10K: 3.95; DescriptiveText: Cortex A9 SOC AM437x; Location X-Coordinate: 0; Location Y-Coordinate: 0; Mfr: TI; MfrNum: AM437XZDN; PACKAGE: 1; Power Pins Visible: False; Primitive: DEFAULT; TIIntPartnumber: 1A0392; Vendor: TI
C47 C48 C61 C62 C70 C71 C101-C108 C112-C116 C121-C124 C136-C140 C143-C151 C156 C171 C177 C190 C196-C198 C228 C229 C231 C232 C235 C236 C270 C271 C277-C282 C284-C288 C290-C292 C294 C315 = 1C_0.01uFCapacitor16V10%0402
C125 C152 = 1C_22uFCapacitor16V10%0805
C128 C130 C131 C153-C155 C160 C162 C165 C168 C170 C180 C182 C184 C187 C189 C272 C297 C305 C307 C309 C311 C313 C472 = 1C_0.1uFCapacitor16V10%0402
J7 = 2H_Header_2x1
R94 R126 = 1R_240OhmResistor1_16W0402
R45 R46 R65 R97-R121 R156 R157 R163 R194 R195 R198 R216-R219 R222-R224 R226-R230 R244 R253 R293 R328 R329 R370 R375 R380 R384 R386 R393-R396 R400-R402 R704 R707 R708 R710-R713 R716-R733 R736-R740 R742 R744 R745 = 1R_ZeroOhmResistor1_16W0402
R125 = 1R_49.9OhmResistor1_16W0402
R220 R221 R389 R702 R703 R705 = 1R_2.2KOhmResistor1_16W0402
U6 U7 = 1A_MT41K256M16HA
C159 C166 C178 C179 C302 C303 = 1C_47uFCapacitor16V20%1206
C161 C163 C164 C167 C169 C176 C181 C183 C185 C186 C188 C195 C227 C230 C304 C306 C308 C310 C312 C317 = 1C_10uFCapacitor16V10%0805
C172 C173 C191 C192 = 1C_22pFCapacitor50V10%SMD0402
C174 C175 C193 C194 C298-C301 = 1C_0.1uFCapacitor50V10%0402
D5 D6 = Diode200mA250V
FB1-FB8 = 1L_FerriteBead_600mA10ohm
J6 J8 = 2J_ConnectorRJ45_Gigabit_0
Q2 Q3 = 1Q_MOSFET_PChan_FDT434P
R141 R142 R179 R180 R387 = 1R_220ohm1_10W1%smd0402
R143 R181 = 1R_100KOhmResistor1_16W0402
R144-R155 R182-R193 = 1R_22OhmResistor1_16W1%0402
R158 R196 R242 R243 R325 R327 R382 R385 = 1R_4.7KOhmResistor1_16W0402
R159 R197 = 1R_12.1KohmResistor1_16W1%0402
R160 R162 R164 R168 R170 R172 R200 R202 R206 R208 R210 R214 R248 R324 R326 R331 R351-R353 R357-R364 R366 R367 R369 R383 R388 R390 R398 R426 = 1R_10KOhmResistor1_16W0402
R161 = 1R_1.5KohmResistor1_16W5%0402
R167 R175 R177 R205 R213 = 1R_1KOhmResistor1_16W0402
U12 U14 = 1A_KSZ9031RNX
U13 U15 = 1A_SN74LVC1G07
Y3 Y4 = 1Y_Crystal25MHzABM3
FB9 FB10 FB17 = 1L_FerBead_180ohm200mA
J26 J27 = 2C_Conn_3.5mm_SJ3524SMT
R225 = 1R_ZeroOhmResistor1_16W0603
U41 = 1A_TLV320AIC3106
A2 = 4P_CameraModuleOV2659_2MpDI
C240 = 1C_15pFCapacitor50V10%smd0402
C241 C242 = 1C_2.2uFCapacitor6.3V10%smd0603
C200 C468 = 1C_1uFCapacitor10V10%0402
J15 = 2C_Conn_FFC_0.3mm_25pos
R255 = 1R_39Kohm1_16W5%smd0402
R256 = 1R_30.1Kohm1_16W1%smd0402
U20 = 1A_SN74AVC1T45
U24 = 1A_TXS0102
U25 = 1A_TPS79301
J10 = 2H_Header10x2_ARMJTAG
R330 R714 = 1R_100ohm1_16W1%SMD0402
R335-R337 R346 R397 = 1R_56KOhmResistor1_16W1%0402
U16 = 1A_LIS331DLH
U27 = 1A_SN74LVC1G04
U33 = 1A_CAT24C256W
C283 C289 C293 = 1C_4.7uFCapacitor16V10%0603
C295 C296 = 1C_18pFCapacitor16V10%0402
C316 = 1C_2.2uF16V10%SMD0805
D11 = 1F_LED_Green
FB14-FB16 = 1L_FerriteBead_220ohm2A
J25 = 2C_MicroUSBAB
R376 = 1R_12Kohm1_16W1%SMD0402
TP23 = 2H_Testpoint_SMD1mmCircle
U9 U19 = 1A_SN74AVC4T245
U11 U17 = 1A_SN74AVC2T244
U36 = 1A_SN74LVC1G00DCK
U37 = 1A_SN74LVC2G07
U38 = 1A_TPD4S012
U39 = 1A_FT2232_QFN
U40 = 1A_93C56EEPROM2Kbit
U46 = 1A_TPS79333
Y5 = 1Y_Crystal12MHzABM3

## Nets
AGND_AUD: C300.2 C301.2 C304.2 C305.2 C306.2 C307.2 C308.2 C309.2 J26.1(P1) J27.1(P1) R225.2(P2) U41.15(AVSS_ADC) U41.20(DRVSS) U41.21(DRVSS) U41.26(AVSS_DAC) U41.TPAD
AGNDCAM: C227.2 C228.2 J15.24 R402.2(P2)
DGND: C47.2 C48.2 C61.2 C62.2 C70.2 C71.2 C101.2 C102.2 C103.2 C104.2 C105.2 C106.2 C107.2 C108.2 C112.2 C113.2 C114.2 C115.2 C116.2 C121.2 C122.2 C123.2 C124.2 C125.2 C130.2 C131.2 C136.2 C137.2 C138.2 C139.2 C140.2 C143.2 C144.2 C145.2 C146.2 C147.2 C148.2 C149.2 C150.2 C151.2 C152.2 C154.2 C155.2 C156.2 C159.2 C160.2 C161.2 C162.2 C163.2 C164.2 C165.2 C166.2 C167.2 C168.2 C169.2 C170.2 C171.2 C172.1 C173.1 C174.1 C175.1 C176.2 C177.2 C178.2 C179.2 C180.2 C181.2 C182.2 C183.2 C184.2 C185.2 C186.2 C187.2 C188.2 C189.2 C190.2 C191.1 C192.1 C193.1 C194.1 C195.2 C196.2 C197.2 C198.2 C200.2 C229.2 C230.2 C231.2 C232.2 C235.2 C236.2 C241.2 C242.2 C270.2 C271.2 C272.2 C277.2 C278.2 C279.2 C280.1 C281.2 C282.1 C283.1 C284.2 C285.2 C286.1 C287.2 C288.2 C289.1 C290.2 C291.2 C292.1 C293.2 C294.1 C295.2 C296.2 C297.2 C310.2 C311.2 C312.2 C313.2 C315.2 C316.2 C317.2 C468.2 C472.2 FB17.2 J6.1 J8.1 J10.8(GND) J10.20(GND) J15.11 J15.MNT1 J15.MNT2 J25.5(GND) R94.1(P1) R125.1(P1) R126.1(P1) R159.2 R167.1(P1) R175.1(P1) R177.1(P1) R197.2 R205.1(P1) R213.1(P1) R219.1(P1) R225.1(P1) R256.1(P1) R351.1(P1) R352.1(P1) R353.1(P1) R357.1(P1) R358.1(P1) R359.1(P1) R360.1(P1) R361.1(P1) R362.1(P1) R363.1(P1) R364.1(P1) R366.1(P1) R367.1(P1) R369.1(P1) R376.2(P2) R382.1(P1) R384.1(P1) R388.1(P1) R398.1(P1) R402.1(P1) R702.1(P1) R705.1(P1) R708.1(P1) R710.1(P1) R711.1(P1) R712.1(P1) R713.1(P1) R716.1(P1) U6.A9(VSS) U6.B1(VSSQ) U6.B3(VSS) U6.B9(VSSQ) U6.D1(VSSQ) U6.D8(VSSQ) U6.E1(VSS) U6.E2(VSSQ) U6.E8(VSSQ) U6.F9(VSSQ) U6.G1(VSSQ) U6.G8(VSS) U6.G9(VSSQ) U6.J2(VSS) U6.J8(VSS) U6.M1(VSS) U6.M9(VSS) U6.P1(VSS) U6.P9(VSS) U6.T1(VSS) U6.T9(VSS) U7.A9(VSS) U7.B1(VSSQ) U7.B3(VSS) U7.B9(VSSQ) U7.D1(VSSQ) U7.D8(VSSQ) U7.E1(VSS) U7.E2(VSSQ) U7.E8(VSSQ) U7.F9(VSSQ) U7.G1(VSSQ) U7.G8(VSS) U7.G9(VSSQ) U7.J2(VSS) U7.J8(VSS) U7.M1(VSS) U7.M9(VSS) U7.P1(VSS) U7.P9(VSS) U7.T1(VSS) U7.T9(VSS) U9.2(1DIR) U9.3(2DIR) U9.8(GND) U9.9(GND) U11.5(GND) U12.13(VSS_PS) U12.29(VSS) U12.49(P_GND) U13.3(GND) U14.13(VSS_PS) U14.29(VSS) U14.49(P_GND) U15.3(GND) U16.5(GND) U16.10(RSV0) U16.12(GND) U16.13(GND) U16.16(GND) U17.5(GND) U19.3(2DIR) U19.8(GND) U19.9(GND) U19.14(2~{OE}) U19.15(1~{OE}) U20.2(GND) U20.5(DIR) U24.2(GND) U25.2(GND) U27.3(GND) U33.1(A0) U33.2(A1) U33.3(A2) U33.4(VSS) U36.3(GND) U37.2(GND) U38.4(GND) U39.1(GND.1) U39.5(GND.2) U39.10(AGND) U39.11(GND.3) U39.13(TEST) U39.15(GND.4) U39.25(GND.5) U39.35(GND.6) U39.47(GND.7) U39.51(GND.8) U39.TPAD U40.5(VSS) U40.7(NC1) U41.42(DVSS) U41.43(SELECT) U46.2(GND) ; also on sheet 9 10 11 12 13 14 15 17 18 19
GND_ETH1: C174.2 C175.2 J6.SHLD1 J6.SHLD2
GND_ETH2: C193.2 C194.2 J8.SHLD1 J8.SHLD2
GNDA_ADC: U1.AE14(ADC0_VREFN) ; also on sheet 9
GNDUSBJ: FB17.1 J25.S1 J25.S2 J25.S3 J25.S4
V1_8D: C229.1 C230.1 C232.1 C236.1 C312.1 C313.1 J15.15 R242.2(P2) R243.2(P2) R248.2(P2) R253.2(P2) R331.2(P2) U20.1(VCCA) U24.3(VCCA) U41.36(DVDD) ; also on sheet 9 18 19
V1_8FTDI: C279.1 C284.1 C287.1 C290.1 C293.1 U39.12(VCORE.1) U39.37(VCORE.2) U39.49(VREGOUT) U39.64(VCORE.3)
V2_8A: C227.1 C228.1 FB10.2 J15.22
V2_8A_EN: R253.1(P1) U25.3(EN)
V2_8A_FB: C240.2 R255.1(P1) R256.2(P2) U25.5(FB)
V2_8A_OUT: C240.1 C241.1 FB10.1 R255.2(P2) U25.6(OUT)
V3_3AUD: C304.1 C305.1 C306.1 C307.1 C308.1 C309.1 FB9.2 U41.16(DRVDD) U41.17(DRVDD) U41.24(DRVDD) U41.25(AVDD_DAC)
V3_3D: C47.1 C61.1 C70.1 C101.1 C108.1 C160.1 C161.1 C177.1 C182.1 C185.1 C196.1 C197.1 C198.1 C231.1 C235.1 C270.1 C271.1 C280.2 C282.2 C310.1 C311.1 D5.1(Cathode) D6.1(Cathode) FB2.1 FB6.1 FB9.1 J10.1(VTREF) R141.2 R142.2 R143.2(P2) R158.2(P2) R160.1(P1) R161.2(P2) R162.1(P1) R164.1(P1) R168.1(P1) R170.1(P1) R172.1(P1) R179.2 R180.2 R181.2(P2) R196.2(P2) R200.1(P1) R202.1(P1) R206.1(P1) R208.1(P1) R210.1(P1) R214.1(P1) R216.2(P2) R220.2(P2) R221.2(P2) R324.2(P2) R325.2(P2) R326.2(P2) R327.2(P2) R335.2(P2) R336.2(P2) R337.2(P2) R346.2(P2) R397.2(P2) R426.2(P2) R707.1(P1) U9.1(VCCA) U11.1(VCCA) U11.3(A2) U12.16(DVDDH) U12.34(DVDDH) U12.40(DVDDH) U13.5(VCC) U14.16(DVDDH) U14.34(DVDDH) U14.40(DVDDH) U15.5(VCC) U16.1(VDD_IO) U16.14(VDD) U16.15(RSV1) U17.8(VCCB) U19.1(VCCA) U19.2(1DIR) U20.6(VCCB) U24.7(VCCB) U27.5(VCC) U33.8(VCC) U36.5(VCC) U37.5(VCC) U41.44(IOVDD) U41.45(MFP0) U41.46(MFP1) ; also on sheet 9 10 11 13 14 15 17 18 19
V3_3FTDI: C48.1 C62.1 C71.1 C107.1 C281.1 C285.1 C288.1 C291.1 C294.2 C297.1 C316.1 FB15.2 FB16.2 R383.2(P2) R390.2(P2) U9.16(VCCB) U11.8(VCCB) U17.1(VCCA) U19.16(VCCB) U39.20(VCCIO.1) U39.31(VCCIO.2) U39.42(VCCIO.3) U39.50(VREGIN) U39.56(VCCIO.4) U40.6(NC2) U40.8(VCC) U46.5(OUT)
VBAT: C242.1 U25.1(IN) ; also on sheet 11 12 14 18 19
VDDA_ADC: R244.1(P1) ; also on sheet 9
VDDR_VREF: C128.2 C130.1 C131.1 C153.2 C154.1 C155.1 C156.1 R702.2(P2) R703.1(P1) U1.T6(DDR_VREF) U6.H1(VREFDQ) U6.M8(VREFCA) U7.H1(VREFDQ) U7.M8(VREFCA)
VDDS_DDR: C102.1 C103.1 C104.1 C105.1 C106.1 C112.1 C113.1 C114.1 C115.1 C116.1 C121.1 C122.1 C123.1 C124.1 C125.1 C128.1 C136.1 C137.1 C138.1 C139.1 C140.1 C143.1 C144.1 C145.1 C146.1 C147.1 C148.1 C149.1 C150.1 C151.1 C152.1 C153.1 J7.2 R703.2(P2) R742.1(P1) U6.A1(VDDQ) U6.A8(VDDQ) U6.B2(VDD) U6.C1(VDDQ) U6.C9(VDDQ) U6.D2(VDDQ) U6.D9(VDD) U6.E9(VDDQ) U6.F1(VDDQ) U6.G7(VDD) U6.H2(VDDQ) U6.H9(VDDQ) U6.K2(VDD) U6.K8(VDD) U6.N1(VDD) U6.N9(VDD) U6.R1(VDD) U6.R9(VDD) U7.A1(VDDQ) U7.A8(VDDQ) U7.B2(VDD) U7.C1(VDDQ) U7.C9(VDDQ) U7.D2(VDDQ) U7.D9(VDD) U7.E9(VDDQ) U7.F1(VDDQ) U7.G7(VDD) U7.H2(VDDQ) U7.H9(VDDQ) U7.K2(VDD) U7.K8(VDD) U7.N1(VDD) U7.N9(VDD) U7.R1(VDD) U7.R9(VDD)
ACCEL_INT1: U16.11(INT1) ; also on sheet 16
ACCEL_INT2: U16.9(INT2) ; also on sheet 16
ADC0_AIN0: R737.1(P1) U1.AA12(ADC0_AIN0)
ADC0_AIN1: R738.1(P1) U1.Y12(ADC0_AIN1)
ADC0_AIN2: R739.1(P1) U1.Y13(ADC0_AIN2)
ADC0_AIN3: R740.1(P1) U1.AA13(ADC0_AIN3)
AM437X_CAM0_DATA0: J15.7 U1.AE18(CAM0_DATA0)
AM437X_CAM0_DATA1: J15.5 U1.AB18(CAM0_DATA1)
AM437X_CAM0_DATA2: J15.4 U1.Y18(CAM0_DATA2)
AM437X_CAM0_DATA3: J15.6 U1.AA18(CAM0_DATA3)
AM437X_CAM0_DATA4: J15.8 U1.AE19(CAM0_DATA4)
AM437X_CAM0_DATA5: J15.10 U1.AD19(CAM0_DATA5)
AM437X_CAM0_DATA6: J15.12 U1.AE20(CAM0_DATA6)
AM437X_CAM0_DATA7: J15.14 U1.AD20(CAM0_DATA7)
AM437X_CAM0_HSYNC: J15.17 U1.AE17(CAM0_HD)
AM437X_CAM0_PCLK: R704.2(P2) U1.AC20(CAM0_PCLK)
AM437X_CAM0_VSYNC: J15.19 U1.AD18(CAM0_VD)
AM437X_CLKOUT1: R230.2(P2) U1.D24(XDMA_EVENT_INTR0/CLKOUT1)
AM437X_DDR_A0: R107.2(P2) U1.N1(DDR_A0)
AM437X_DDR_A1: R108.2(P2) U1.L1(DDR_A1)
AM437X_DDR_A2: R109.2(P2) U1.L2(DDR_A2)
AM437X_DDR_A3: R110.2(P2) U1.P2(DDR_A3)
AM437X_DDR_A4: R111.2(P2) U1.P1(DDR_A4)
AM437X_DDR_A5: R112.2(P2) U1.R5(DDR_A5)
AM437X_DDR_A6: R113.2(P2) U1.R4(DDR_A6)
AM437X_DDR_A7: R114.2(P2) U1.R3(DDR_A7)
AM437X_DDR_A8: R115.2(P2) U1.R2(DDR_A8)
AM437X_DDR_A9: R116.2(P2) U1.R1(DDR_A9)
AM437X_DDR_A10: R117.2(P2) U1.M6(DDR_A10)
AM437X_DDR_A11: R118.2(P2) U1.T5(DDR_A11)
AM437X_DDR_A12: R119.2(P2) U1.T4(DDR_A12)
AM437X_DDR_A13: R120.2(P2) U1.N5(DDR_A13)
AM437X_DDR_A14: R121.2(P2) U1.T3(DDR_A14)
AM437X_DDR_BA0: R104.2(P2) U1.K1(DDR_BA0)
AM437X_DDR_BA1: R105.2(P2) U1.K2(DDR_BA1)
AM437X_DDR_BA2: R106.2(P2) U1.K3(DDR_BA2)
AM437X_DDR_CASN: R101.2(P2) U1.N3(DDR_CASn)
AM437X_DDR_CKE: R97.2(P2) U1.M3(DDR_CKE0)
AM437X_DDR_CLK: R98.2(P2) U1.M2(DDR_CK)
AM437X_DDR_CLKn: R99.2(P2) U1.M1(DDR_CKn)
AM437X_DDR_CS0n: R100.2(P2) U1.M5(DDR_CSN0)
AM437X_DDR_RASN: R102.2(P2) U1.N2(DDR_RASn)
AM437X_DDR_WEn: R103.2(P2) U1.N4(DDR_WEn)
AM437X_I2C0_SCL: U33.6(SCL) ; also on sheet 18
AM437X_I2C0_SDA: U33.5(SDA) ; also on sheet 18
AM437X_I2C1_SCL: R220.1(P1) R222.1(P1) U1.T20(SPI0_CS0/I2C1_SCL)
AM437X_I2C1_SDA: R221.1(P1) R223.1(P1) U1.T21(SPI0_D1/I2C1_SDA)
AM437X_LCD_AC_BIAS_EN: R369.2(P2) ; also on sheet 14
AM437X_LCD_DATA0: R351.2(P2) ; also on sheet 14
AM437X_LCD_DATA1: R352.2(P2) ; also on sheet 14
AM437X_LCD_DATA2: R353.2(P2) ; also on sheet 14
AM437X_LCD_DATA3: R335.1(P1) ; also on sheet 14
AM437X_LCD_DATA4: R336.1(P1) ; also on sheet 14
AM437X_LCD_DATA5: R337.1(P1) ; also on sheet 14
AM437X_LCD_DATA6: R357.2(P2) ; also on sheet 14
AM437X_LCD_DATA7: R358.2(P2) ; also on sheet 14
AM437X_LCD_DATA8: R359.2(P2) ; also on sheet 14
AM437X_LCD_DATA9: R360.2(P2) ; also on sheet 14
AM437X_LCD_DATA10: R361.2(P2) ; also on sheet 14
AM437X_LCD_DATA11: R362.2(P2) ; also on sheet 14
AM437X_LCD_DATA12: R363.2(P2) ; also on sheet 14
AM437X_LCD_DATA13: R364.2(P2) ; also on sheet 14
AM437X_LCD_DATA14: R346.1(P1) ; also on sheet 14
AM437X_LCD_DATA15: R366.2(P2) ; also on sheet 14
AM437X_LCD_HSYNC: R397.1(P1) ; also on sheet 14
AM437X_LCD_VSYNC: R367.2(P2) ; also on sheet 14
AM437X_MCASP1_ACLKX: R226.2(P2) U1.B14(GMII1_CRS/MCASP1_ACLKX)
AM437X_MCASP1_AXR2: R228.2(P2) U1.D16(GMII1_COL/MCASP1_AXR2)
AM437X_MCASP1_AXR3: R229.2(P2) U1.A16(RMII1_REFCLK/MCASP1_AXR3)
AM437X_MCASP1_FSX: R227.2(P2) U1.B13(GMII1_RXERR/MCASP1_FSX)
AM437X_RGMII1_RXCLK: R148.2(P2) U1.D13(MII1_RXCLK/RGMII1_RCLK)
AM437X_RGMII1_RXCTL: R151.2(P2) U1.A15(MII1_RXDV/RGMII1_RXCTL)
AM437X_RGMII1_RXD0: R152.2(P2) U1.F17(MII1_RXD0/RGMII1_RD0)
AM437X_RGMII1_RXD1: R153.2(P2) U1.B16(MII1_RXD1/RGMII1_RD1)
AM437X_RGMII1_RXD2: R154.2(P2) U1.E16(MII1_RXD2/RGMII1_RD2)
AM437X_RGMII1_RXD3: R155.2(P2) U1.C14(MII1_RXD3/RGMII1_RD3)
AM437X_RGMII1_TXCLK: R144.2(P2) U1.D14(MII1_TXCLK/RGMII1_TXCLK)
AM437X_RGMII1_TXCTL: R145.2(P2) U1.A13(MII1_TXEN/RGMII1_TXCTL)
AM437X_RGMII1_TXD0: R146.2(P2) U1.B15(MII1_TXD0/RGMII1_TD0)
AM437X_RGMII1_TXD1: R147.2(P2) U1.A14(MII1_TXD1/RGMII1_TD1)
AM437X_RGMII1_TXD2: R149.2(P2) U1.C13(MII1_TXD2/RGMII1_TD2)
AM437X_RGMII1_TXD3: R150.2(P2) U1.C16(MII1_TXD3/RGMII1_TD3)
AM437X_RGMII2_RXCLK: R189.2(P2) U1.F6(GPMC_A7/RGMII2_RCLK)
AM437X_RGMII2_RXCTL: R190.2(P2) U1.C5(GPMC_A1/RGMII2_RCTL)
AM437X_RGMII2_RXD0: R183.2(P2) U1.D8(GPMC_A11/RGMII2_RD0)
AM437X_RGMII2_RXD1: R191.2(P2) U1.G8(GPMC_A10/RGMII2_RD1)
AM437X_RGMII2_RXD2: R192.2(P2) U1.B4(GPMC_A9/RGMII2_RD2)
AM437X_RGMII2_RXD3: R193.2(P2) U1.F7(GPMC_A8/RGMII2_RD3)
AM437X_RGMII2_TXCLK: R182.2(P2) U1.E8(GPMC_A6/RGMII2_TCLK)
AM437X_RGMII2_TXCTL: R184.2(P2) U1.C3(GPMC_A0/RGMII2_TCTL)
AM437X_RGMII2_TXD0: R185.2(P2) U1.E7(GPMC_A5/RGMII2_TD0)
AM437X_RGMII2_TXD1: R186.2(P2) U1.D7(GPMC_A4/RGMII2_TD1)
AM437X_RGMII2_TXD2: R187.2(P2) U1.A4(GPMC_A3/RGMII2_TD2)
AM437X_RGMII2_TXD3: R188.2(P2) U1.C6(GPMC_A2/RGMII2_TD3)
AUD_HPLOUT: C303.1 U41.18(HPLOUT)
AUD_HPLOUT_JCK: C303.2 J27.2(P2)
AUD_HPROUT: C302.1 U41.23(HPROUT)
AUD_HPROUT_JCK: C302.2 J27.3(P3)
AUD_LINEINL: C299.1 U41.3(LINE1LP)
AUD_LINEINL_JCK: C299.2 J26.2(P2)
AUD_LINEINR: C298.1 U41.5(LINE1RP)
AUD_LINEINR_JCK: C298.2 J26.3(P3)
AUD_RESETn: R224.1(P1) U41.33(RESETn)
AUDIO_BCLK: R226.1(P1) U41.38(BCLK)
AUDIO_DIN: R228.1(P1) U41.40(DIN)
AUDIO_DOUT: R229.1(P1) U41.41(DOUT)
AUDIO_WCLK: R227.1(P1) U41.39(WCLK)
CAM0_GIO0: R400.2(P2) R705.2(P2) U1.AB20(CAM1_DATA0/GPIO)
CAM0_PCLK: J15.9 R704.1(P1)
CAM_SRCCLK: R401.2(P2) U20.3(A)
DDR_A0: R107.1(P1) U6.N3(A0) U7.N3(A0)
DDR_A1: R108.1(P1) U6.P7(A1) U7.P7(A1)
DDR_A2: R109.1(P1) U6.P3(A2) U7.P3(A2)
DDR_A3: R110.1(P1) U6.N2(A3) U7.N2(A3)
DDR_A4: R111.1(P1) U6.P8(A4) U7.P8(A4)
DDR_A5: R112.1(P1) U6.P2(A5) U7.P2(A5)
DDR_A6: R113.1(P1) U6.R8(A6) U7.R8(A6)
DDR_A7: R114.1(P1) U6.R2(A7) U7.R2(A7)
DDR_A8: R115.1(P1) U6.T8(A8) U7.T8(A8)
DDR_A9: R116.1(P1) U6.R3(A9) U7.R3(A9)
DDR_A10: R117.1(P1) U6.L7(A10/AP) U7.L7(A10/AP)
DDR_A11: R118.1(P1) U6.R7(A11) U7.R7(A11)
DDR_A12: R119.1(P1) U6.N7(A12/~{BC}) U7.N7(A12/~{BC})
DDR_A13: R120.1(P1) U6.T3(A13) U7.T3(A13)
DDR_A14: R121.1(P1) U6.T7(A14) U7.T7(A14)
DDR_BA0: R104.1(P1) U6.M2(BA0) U7.M2(BA0)
DDR_BA1: R105.1(P1) U6.N8(BA1) U7.N8(BA1)
DDR_BA2: R106.1(P1) U6.M3(BA2) U7.M3(BA2)
DDR_CASn: R101.1(P1) U6.K3(CASn) U7.K3(CASn)
DDR_CKE: R97.1(P1) U6.K9(CKE) U7.K9(CKE)
DDR_CLK: R98.1(P1) U6.J7(CK) U7.J7(CK)
DDR_CLKn: R99.1(P1) U6.K7(CKn) U7.K7(CKn)
DDR_CS0n: R100.1(P1) U6.L2(CSn) U7.L2(CSn)
DDR_D0: U1.E3(DDR_D0) U6.E3(DQ0)
DDR_D1: U1.G2(DDR_D6) U6.F7(DQ1)
DDR_D2: U1.G4(DDR_D4) U6.F2(DQ2)
DDR_D3: U1.G1(DDR_D7) U6.F8(DQ3)
DDR_D4: U1.F3(DDR_D3) U6.H3(DQ4)
DDR_D5: U1.E1(DDR_D2) U6.H8(DQ5)
DDR_D6: U1.G3(DDR_D5) U6.G2(DQ6)
DDR_D7: U1.E2(DDR_D1) U6.H7(DQ7)
DDR_D8: U1.K5(DDR_D14) U6.D7(DQ8)
DDR_D9: U1.J4(DDR_D11) U6.C3(DQ9)
DDR_D10: U1.K6(DDR_D13) U6.C8(DQ10)
DDR_D11: U1.K4(DDR_D15) U6.C2(DQ11)
DDR_D12: U1.H1(DDR_D8) U6.A7(DQ12)
DDR_D13: U1.J3(DDR_D12) U6.A2(DQ13)
DDR_D14: U1.J6(DDR_D9) U6.B8(DQ14)
DDR_D15: U1.J5(DDR_D10) U6.A3(DQ15)
DDR_D16: U1.V2(DDR_D19) U7.E3(DQ0)
DDR_D17: U1.V5(DDR_D16) U7.F7(DQ1)
DDR_D18: U1.V3(DDR_D18) U7.F2(DQ2)
DDR_D19: U1.W6(DDR_D23) U7.F8(DQ3)
DDR_D20: U1.V4(DDR_D17) U7.H3(DQ4)
DDR_D21: U1.W5(DDR_D22) U7.H8(DQ5)
DDR_D22: U1.V1(DDR_D20) U7.G2(DQ6)
DDR_D23: U1.W4(DDR_D21) U7.H7(DQ7)
DDR_D24: U1.AB2(DDR_D28) U7.D7(DQ8)
DDR_D25: U1.Y2(DDR_D24) U7.C3(DQ9)
DDR_D26: U1.AA3(DDR_D27) U7.C8(DQ10)
DDR_D27: U1.Y4(DDR_D26) U7.C2(DQ11)
DDR_D28: U1.AC1(DDR_D30) U7.A7(DQ12)
DDR_D29: U1.Y3(DDR_D25) U7.A2(DQ13)
DDR_D30: U1.AC2(DDR_D31) U7.B8(DQ14)
DDR_D31: U1.AB1(DDR_D29) U7.A3(DQ15)
DDR_DQM0: U1.F4(DDR_DQM0) U6.E7(LDM)
DDR_DQM1: U1.H2(DDR_DQM1) U6.D3(UDM)
DDR_DQM2: U1.V6(DDR_DQM2) U7.E7(LDM)
DDR_DQM3: U1.Y1(DDR_DQM3) U7.D3(UDM)
DDR_DQS0: U1.F2(DDR_DQS0) U6.F3(LDQS)
DDR_DQS1: U1.J2(DDR_DQS1) U6.C7(UDQS)
DDR_DQS2: U1.W1(DDR_DQS2) U7.F3(LDQS)
DDR_DQS3: U1.AA1(DDR_DQS3) U7.C7(UDQS)
DDR_DQSN0: U1.F1(DDR_DQS0n) U6.G3(LDQSn)
DDR_DQSN1: U1.J1(DDR_DQS1n) U6.B7(UDQSn)
DDR_DQSN2: U1.W2(DDR_DQS2n) U7.G3(LDQSn)
DDR_DQSN3: U1.AA2(DDR_DQS3n) U7.B7(UDQSn)
DDR_ODT: U1.U1(DDR_ODT0) U6.K1(ODT) U7.K1(ODT)
DDR_RASn: R102.1(P1) U6.J3(RASn) U7.J3(RASn)
DDR_RESETn: U1.T1(DDR_RESETn) U6.T2(RESETn) U7.T2(RESETn)
DDR_WEn: R103.1(P1) U6.L3(WEn) U7.L3(WEn)
EECS: U39.63(EECS) U40.1(CS)
EEDATA: R389.1(P1) U39.61(EEDATA) U40.3(DI)
EESK: U39.62(EESK) U40.2(CLK)
EMU_RSTn: C272.1 R326.1(P1) R330.1(P1) R721.2(P2)
EMU_USB_DM: J25.2(DM) U38.2(D-) U39.7(DM)
EMU_USB_DP: J25.3(DP) U38.1(D+) U39.8(DP)
ETH1_INTn: R163.2(P2) ; also on sheet 16
ETH1_LDO_O: Q2.G(GATE) U12.43(LDO_O)
ETH1_RESETn: C176.1 D5.2(Anode) R143.1(P1) U12.42(RESET_N) U13.4(Y)
ETH1_RXCLK: R148.1(P1) R172.2(P2) U12.35(RX_CLK)
ETH1_RXD0: R152.1(P1) R162.2(P2) U12.32(RXD0)
ETH1_RXD1: R153.1(P1) R164.2(P2) U12.31(RXD1)
ETH1_RXD2: R154.1(P1) R168.2(P2) U12.28(RXD2)
ETH1_RXD3: R155.1(P1) R170.2(P2) U12.27(RXD3)
ETH1_RXDV: R151.1(P1) R167.2(P2) U12.33(RX_DV)
ETH1_TXCLK: R144.1(P1) U12.24(GTX_CLK)
ETH1_TXD0: R146.1(P1) U12.19(TXD0)
ETH1_TXD1: R147.1(P1) U12.20(TXD1)
ETH1_TXD2: R149.1(P1) U12.21(TXD2)
ETH1_TXD3: R150.1(P1) U12.22(TXD3)
ETH1_TXEN: R145.1(P1) U12.25(TX_EN)
ETH2_INTn: R198.2(P2) ; also on sheet 16
ETH2_LDO_O: Q3.G(GATE) U14.43(LDO_O)
ETH2_RESETn: C195.1 D6.2(Anode) R181.1(P1) U14.42(RESET_N) U15.4(Y)
ETH2_RXCLK: R189.1(P1) R210.2(P2) U14.35(RX_CLK)
ETH2_RXD0: R183.1(P1) R200.2(P2) U14.32(RXD0)
ETH2_RXD1: R191.1(P1) R202.2(P2) U14.31(RXD1)
ETH2_RXD2: R192.1(P1) R206.2(P2) U14.28(RXD2)
ETH2_RXD3: R193.1(P1) R208.2(P2) U14.27(RXD3)
ETH2_RXDV: R190.1(P1) R205.2(P2) U14.33(RX_DV)
ETH2_TXCLK: R182.1(P1) U14.24(GTX_CLK)
ETH2_TXD0: R185.1(P1) U14.19(TXD0)
ETH2_TXD1: R186.1(P1) U14.20(TXD1)
ETH2_TXD2: R187.1(P1) U14.21(TXD2)
ETH2_TXD3: R188.1(P1) U14.22(TXD3)
ETH2_TXEN: R184.1(P1) U14.25(TX_EN)
ETH_MDIO_CLK: R156.2(P2) R160.2(P2) R194.2(P2) U1.B17(MDIO_CLK)
ETH_MDIO_DATA: R157.2(P2) R161.1(P1) R195.2(P2) U1.A17(MDIO_DATA)
ETHER1_D0N: J6.10 U12.3(TXRXM_A)
ETHER1_D0P: J6.9 U12.2(TXRXP_A)
ETHER1_D1N: J6.8 U12.6(TXRXM_B)
ETHER1_D1P: J6.7 U12.5(TXRXP_B)
ETHER1_D2N: J6.6 U12.8(TXRXM_C)
ETHER1_D2P: J6.5 U12.7(TXRXP_C)
ETHER1_D3N: J6.4 U12.11(TXRXM_D)
ETHER1_D3P: J6.3 U12.10(TXRXP_D)
ETHER2_D0N: J8.10 U14.3(TXRXM_A)
ETHER2_D0P: J8.9 U14.2(TXRXP_A)
ETHER2_D1N: J8.8 U14.6(TXRXM_B)
ETHER2_D1P: J8.7 U14.5(TXRXP_B)
ETHER2_D2N: J8.6 U14.8(TXRXM_C)
ETHER2_D2P: J8.5 U14.7(TXRXP_C)
ETHER2_D3N: J8.4 U14.11(TXRXM_D)
ETHER2_D3P: J8.3 U14.10(TXRXP_D)
F_ADBUS0: U9.10(2B2) U39.16(ADBUS0)
F_ADBUS1: U9.11(2B1) U39.17(ADBUS1)
F_ADBUS2: U11.7(B1) U39.18(ADBUS2)
F_ADBUS3: U9.12(1B2) U39.19(ADBUS3)
F_ADBUS4: U9.13(1B1) U39.21(ADBUS4)
F_ADBUS5: R375.2(P2) U39.26(ACBUS0)
F_ADBUS6: U17.2(A1) U39.23(ADBUS6)
F_ADBUS7: U17.3(A2) U39.30(ACBUS4)
FT_SRESET: R375.1(P1) R382.2(P2) U36.1(A)
FT_SRESETB: R370.2(P2) U37.6(1Y)
FT_SRESETn: U36.4(Y) U37.1(1A)
FT_VBUS: R386.1(P1) U36.2(B)
FTDI_REF: R376.1(P1) U39.6(REF)
FTDI_VPHY: C283.2 C286.2 FB15.1 U39.4(VPHY)
FTDI_VPLL: C289.2 C292.2 FB16.1 U39.9(VPLL)
FTDI_XTIN: C295.1 U39.2(XTIN) Y5.1
FTDI_XTOUT: C296.1 U39.3(XTOUT) Y5.2
GP_I2C_SCL: R217.2(P2) R222.2(P2) R728.1(P1) U24.8(B1) U41.1(SCL) ; also on sheet 14
GP_I2C_SDA: R218.2(P2) R223.2(P2) R729.1(P1) U24.1(B2) U41.2(SDA) ; also on sheet 14
GPIO0: R727.1(P1) ; also on sheet 16
GPIO1: R731.1(P1) ; also on sheet 16
GPIO2: R732.1(P1) ; also on sheet 16
GPIO3: R733.1(P1) ; also on sheet 16
GPIO4: R744.1(P1) ; also on sheet 16
GPIO5: R745.1(P1) ; also on sheet 16
GPIO6: R736.1(P1) ; also on sheet 16
I2C_SCL_ACCEL: R217.1(P1) U16.4(SCL/SPC)
I2C_SDA_ACCEL: R218.1(P1) U16.6(SDA/SDI/SDO)
JTAG_EMU0: R46.1(P1) U1.N23(JTAG_EMU0)
JTAG_EMU1: R45.1(P1) U1.T24(JTAG_EMU1)
JTAG_TCK: R328.2(P2) R329.2(P2) U1.AA25(JTAG_TCK) U9.7(2A2)
JTAG_TDI: R719.2(P2) U1.Y20(JTAG_TDI) U9.6(2A1)
JTAG_TDO: R723.2(P2) U1.AA24(JTAG_TDO) U11.2(A1)
JTAG_TMS: R325.1(P1) R718.2(P2) U1.Y24(JTAG_TMS) U9.5(1A2)
JTAG_TRSTn: R327.1(P1) R717.2(P2) U1.Y25(JTAG_TRSTn) U9.4(1A1)
JTAGPOD_DET: R65.1(P1) U27.4(Y)
PERIPH_SRC_CLK: R230.1(P1) U20.4(B) U41.37(MCLK)
PHY1_LED_ACTn: J6.12 R177.2(P2) U12.17(LED1_/_PME_N1)
PHY1_LED_LINKn: J6.13 R175.2(P2) U12.15(LED2)
PHY2_LED_ACTn: J8.12 R214.2(P2) U14.17(LED1_/_PME_N1)
PHY2_LED_LINKn: J8.13 R213.2(P2) U14.15(LED2)
RTCK: R329.1(P1) R720.2(P2)
SENSOR_PWDN: J15.18 R400.1(P1)
SENSOR_RESET: C468.1 J15.20 R331.1(P1)
SENSOR_SIO_C: J15.21 R242.1(P1) U24.5(A1)
SENSOR_SIO_D: J15.23 R243.1(P1) U24.4(A2)
SENSOR_XCLK: J15.13 R401.1(P1)
SPI2_CS0: R726.1(P1) U1.T23(SPI2_CS0)
SPI2_D0: R724.1(P1) U1.P22(SPI2_D0)
SPI2_D1: R725.1(P1) U1.P20(SPI2_D1)
SPI2_SCLK: R730.1(P1) U1.N20(SPI2_SCLK)
SYS_RESETn: R224.2(P2) R370.1(P1) U13.2(A) U15.2(A) ; also on sheet 15
TCK: R328.1(P1) R722.2(P2)
USBJTAG_ENn: R65.2(P2) U9.14(2~{OE}) U9.15(1~{OE}) U11.4(~{OE}) U17.4(~{OE})
VDCDC3: J7.1 R742.2(P2) ; also on sheet 18
VETH1_AVDDH: C162.1 C163.1 C166.1 FB2.2 Q2.S(SOURCE) U12.1(AVDDH) U12.12(AVDDH) U12.47(AVDDH)
VETH1_AVDDL: C167.1 C168.1 FB4.2 U12.4(AVDDL) U12.9(AVDDL)
VETH1_AVDDL_PLL: C169.1 C170.1 C171.1 FB1.2 U12.44(AVDDL_PLL)
VETH1_AVDDL_PMOS: C159.1 FB1.1 FB3.1 FB4.1 Q2.D1(DRAIN1) Q2.D2(DRAIN2)
VETH1_DVDDL: C164.1 C165.1 FB3.2 U12.14(DVDDL) U12.18(DVDDL) U12.23(DVDDL) U12.26(DVDDL) U12.30(DVDDL) U12.39(DVDDL)
VETH2_AVDDH: C179.1 C180.1 C181.1 FB6.2 Q3.S(SOURCE) U14.1(AVDDH) U14.12(AVDDH) U14.47(AVDDH)
VETH2_AVDDL: C186.1 C187.1 FB8.2 U14.4(AVDDL) U14.9(AVDDL)
VETH2_AVDDL_PLL: C188.1 C189.1 C190.1 FB5.2 U14.44(AVDDL_PLL)
VETH2_AVDDL_PMOS: C178.1 FB5.1 FB7.1 FB8.1 Q3.D1(DRAIN1) Q3.D2(DRAIN2)
VETH2_DVDDL: C183.1 C184.1 FB7.2 U14.14(DVDDL) U14.18(DVDDL) U14.23(DVDDL) U14.26(DVDDL) U14.30(DVDDL) U14.39(DVDDL)
VUSB_FTDI: C278.1 C317.1 D11.2(Anode) FB14.2 R293.1(P1) R385.2(P2) U46.1(IN)
VUSB_JTAG: C277.1 FB14.1 J25.1(VBUS) U38.6(VBUS)
N12595082: R125.2(P2) U1.AC3(DDR_VTP)
N12957779: R380.2(P2) U39.28(ACBUS2)
N12957783: R380.1(P1) R398.2(P2) U11.6(B2)
N12957791: R384.2(P2) U39.32(ACBUS5)
N12957851: R385.1(P1) R386.2(P2) R388.2(P2) U39.59(BCBUS7)
N12958009: R383.1(P1) U39.14(RESET#)
N12958129: D11.1(Cathode) R387.2
N12958219: R389.2(P2) R390.1(P1) U40.4(DO)
N12958339: TP23.1 U39.36(SUSPEND#)
N12958347: R387.1 U39.60(PWREN#)
N14606304: R94.2(P2) U6.L8(ZQ)
N14617357: R126.2(P2) U7.L8(ZQ)
N15706128: J10.2(VSPLY) R707.2(P2) R728.2(P2)
N15748500: R248.1(P1) U24.6(OE)
N16866661: R156.1(P1) U12.36(MDC)
N16866667: R157.1(P1) U12.37(MDIO)
N16866673: R159.1 U12.48(ISET)
N16878061: J6.11 R142.1
N16878071: J6.14 R141.1
N16912258: R158.1(P1) R163.1(P1) U12.38(INT_N_/_PME_N2)
N16913421: C172.2 U12.46(XI) Y3.1
N16913742: C173.2 U12.45(XO) Y3.2
N16915316: R194.1(P1) U14.36(MDC)
N16915318: R195.1(P1) U14.37(MDIO)
N16915327: R197.1 U14.48(ISET)
N16915495: R196.1(P1) R198.1(P1) U14.38(INT_N_/_PME_N2)
N16915532: C191.2 U14.46(XI) Y4.1
N16915553: C192.2 U14.45(XO) Y4.2
N16915797: J8.11 R180.1
N16915823: J8.14 R179.1
N16963943: C300.1 U41.6(LINE1RM)
N16963949: C301.1 U41.4(LINE1LM)
N17324141: J10.4(GND) R708.2(P2) R729.2(P2)
N17324171: J10.6(GND) R710.2(P2) R730.2(P2)
N17324231: J10.12(GND) R711.2(P2) R737.2(P2)
N17324241: J10.14(GND) R713.2(P2) R738.2(P2)
N17324243: J10.16(GND) R712.2(P2) R739.2(P2)
N17324295: J10.18(GND) R716.2(P2) R740.2(P2)
N17325601: J10.3(nTRST) R717.1(P1) R724.2(P2)
N17325611: J10.5(TDI) R719.1(P1) R725.2(P2)
N17325613: J10.7(TMS) R718.1(P1) R726.2(P2)
N17325631: J10.9(TCK) R722.1(P1) R727.2(P2)
N17325633: J10.11(RTCK) R720.1(P1) R731.2(P2)
N17325635: J10.13(TDO) R723.1(P1) R732.2(P2)
N17325637: J10.15(nSRST) R721.1(P1) R733.2(P2)
N17325659: J10.17(DBGRQ) R744.2(P2)
N17325661: J10.19(DBGACK) R745.2(P2)
N17326933: J10.10(GND) R714.2(P2) R736.2(P2)
N17358478: R393.2(P2) U39.38(BDBUS0)
N17358484: R393.1(P1) U19.11(2B1)
N17358490: R394.2(P2) U39.39(BDBUS1)
N17358493: R394.1(P1) U19.13(1B1)
N17358502: R395.2(P2) U39.40(BDBUS2)
N17358505: R396.2(P2) U39.41(BDBUS3)
N17358508: R395.1(P1) U19.10(2B2)
N17358521: R396.1(P1) U19.12(1B2)
N17543471: R244.2(P2) U1.AD14(ADC0_VREFP)
N17543767: R216.1(P1) U16.8(CS)
N17543769: R219.2(P2) U16.7(SDO/SA0)
N17655690: C472.1 U25.4(NR)
N17677073: R293.2(P2) U46.3(EN)
N17677078: C315.1 U46.4(NR)
N17707024: C200.1 R426.1(P1) R714.1(P1) U27.2(A)
N17726432: U1.J24(UART0_TXD) U19.4(1A1)
N17726440: U1.K25(UART0_RXD) U19.6(2A1)
N17726592: U1.L25(UART0_CTSn) U19.7(2A2)
N17726600: U1.J25(UART0_RTSn) U19.5(1A2)
N17726934: R46.2(P2) U17.7(B1)
N17726936: R45.2(P2) U17.6(B2)
N17797546: J25.4(ID) U38.3(ID)
N18136628: R324.1(P1) U33.7(WP)

Not connected (* = marked no-connect by the designer): J6 2; J8 2; J15 1* 2* 3* 16* 25*; J26 10(P10)*; J27 10(P10)*; R330 2(P2); U1 AA15(ADC1_AIN4)* AA16(ADC1_AIN2)* AB13(ADC0_AIN4)* AB15(ADC1_AIN3)* AB16(ADC1_AIN1)* AC13(ADC0_AIN5)* AC16(ADC1_AIN0)* AD13(ADC0_AIN6)* AD15(ADC1_VREFN)* AD16(ADC1_AIN7)* AE13(ADC0_AIN7)* AE15(ADC1_VREFP)* AE16(ADC1_AIN6)* M4(DDR_CSN1) N6(DDR_CKE1) T2(DDR_A15) U2(DDR_ODT1) Y15(ADC1_AIN5)*; U6 J1(NU0) J9(NU1) L1(NU2) L9(NU3) M7(NU4); U7 J1(NU0)* J9(NU1)* L1(NU2)* L9(NU3)* M7(NU4)*; U12 41(CLK125_NDO); U13 1(NC); U14 41(CLK125_NDO)*; U15 1(NC); U16 2(NC0)* 3(NC1)*; U27 1(NC)*; U38 5(NC)*; U39 22(ADBUS5) 24(ADBUS7) 27(ACBUS1) 29(ACBUS3) 33(ACBUS6) 34(ACBUS7) 43(BDBUS4) 44(BDBUS5) 45(BDBUS6) 46(BDBUS7) 48(BCBUS0) 52(BCBUS1) 53(BCBUS2) 54(BCBUS3) 55(BCBUS4) 57(BCBUS5) 58(BCBUS6); U41 7(LINE2LP)* 8(LINE2LM)* 9(LINE2RP)* 10(LINE2RM)* 11(MIC3L)* 12(MICDET)* 13(MICBIAS)* 14(MIC3R)* 19(HPLCOM)* 22(HPRCOM)* 27(MONO_LOP)* 28(MONO_LOM)* 29(LEFT_LOP)* 30(LEFT_LOM)* 31(RIGHT_ROP)* 32(RIGHT_ROM)* 34(GPIO2)* 35(GPIO1)* 47(MFP2)* 48(MFP3)*

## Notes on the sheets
sheet 2
- ARM MPU AM437X Starter Kit EVM
- -See the Hardware User Guide for board details
- -See the PCB Build Specification for PCB Details
sheet 4
- Audio
  Headphone Out
- Audio
  Line in
sheet 5
- USB JTAG
sheet 6
- Note: DDR Data reordered for
  routing. See Hardware User's Guide
sheet 7
- ID Memory
- Boot Configuration
